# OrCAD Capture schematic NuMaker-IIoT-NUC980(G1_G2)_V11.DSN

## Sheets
1 Block Diagram: size A; title: NK-980IOT; rev: 1.0; company: nuvoTon Technology Corp.; note: Block Diagram
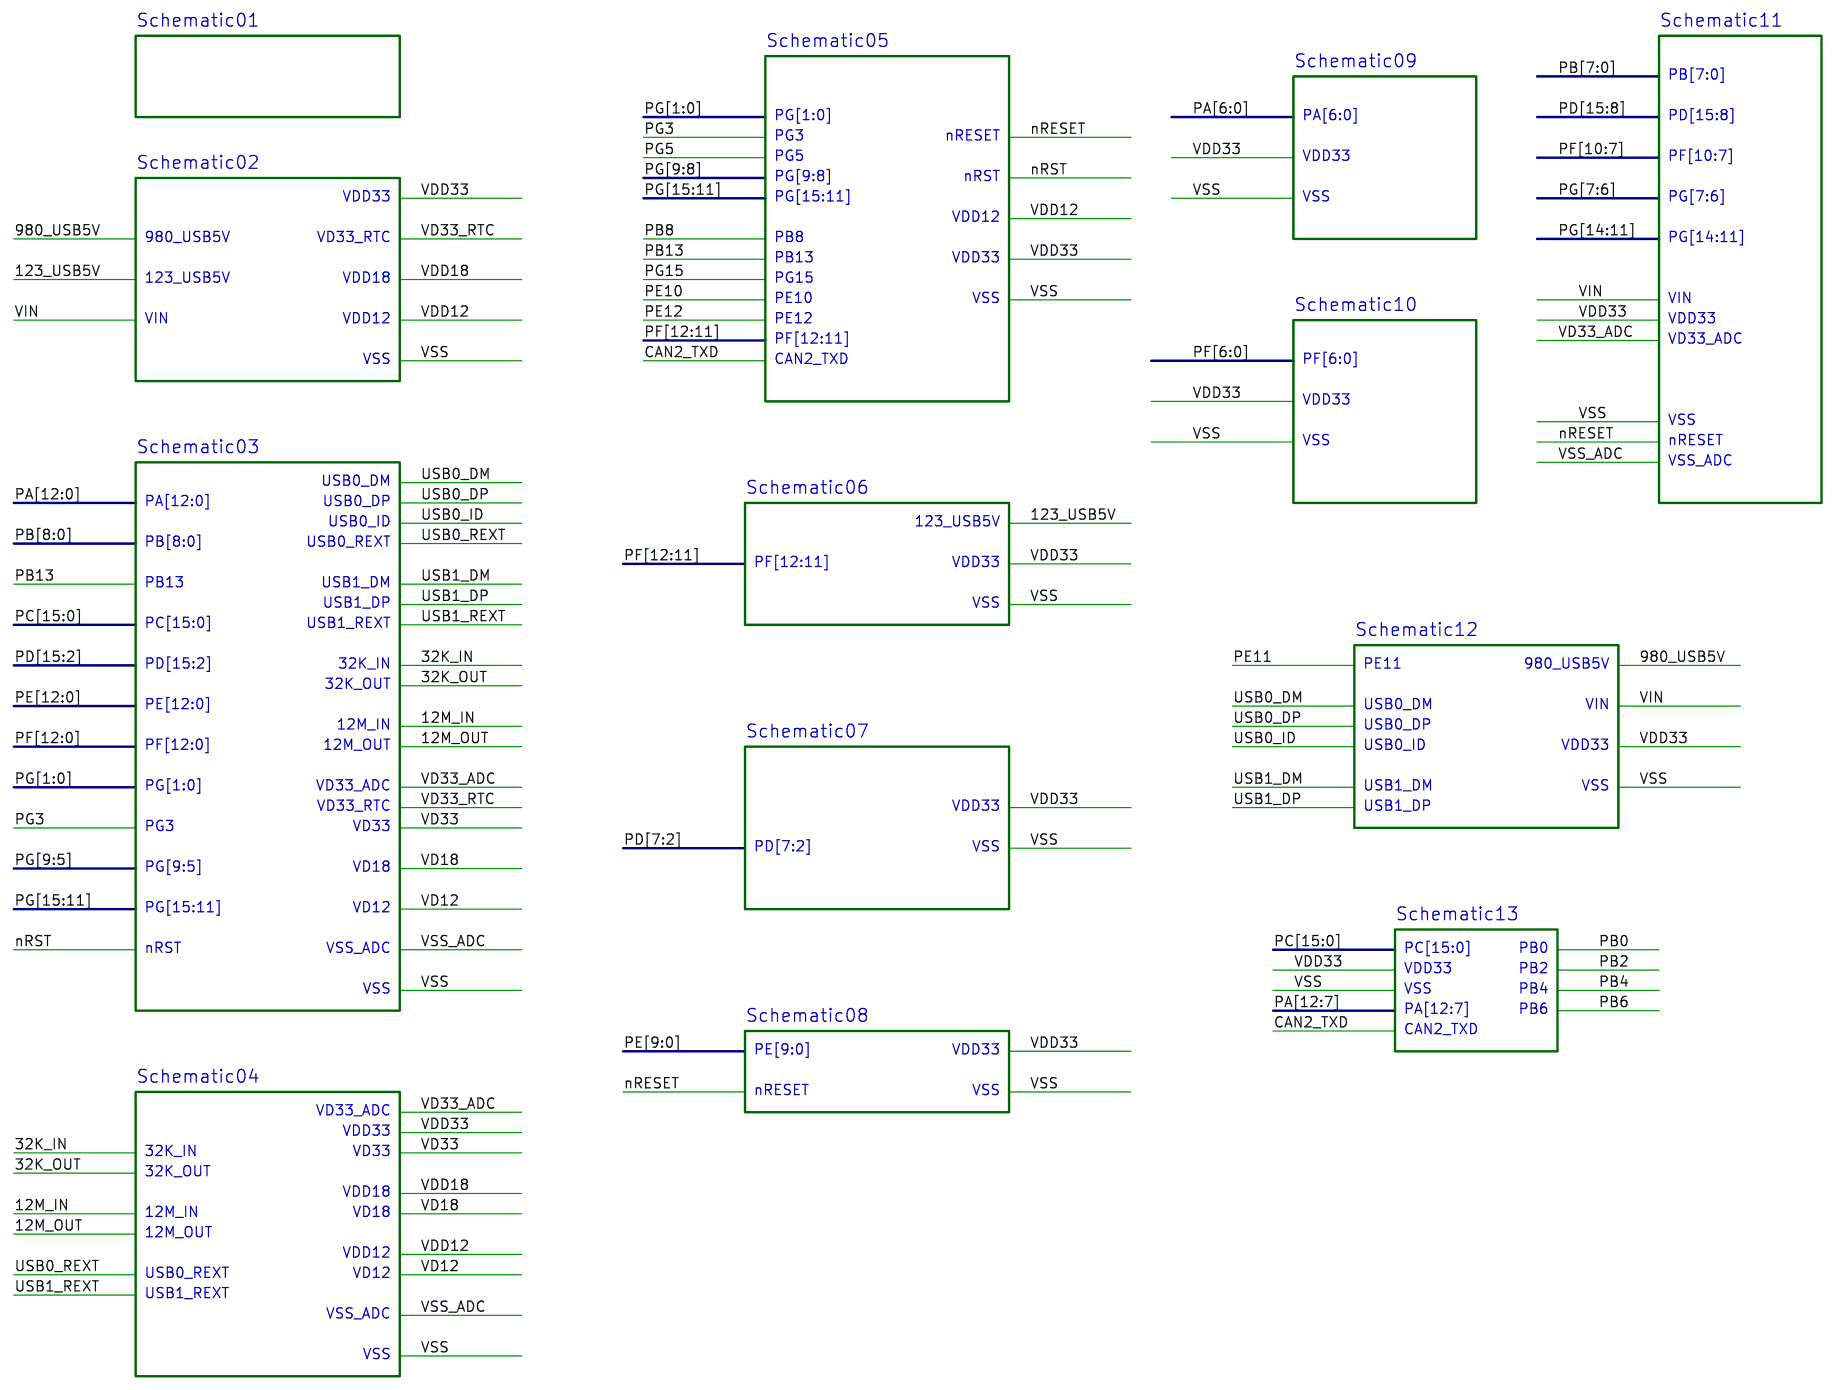
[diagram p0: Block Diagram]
2 Arduino Uno: size A; note: Arduino Uno; block Schematic11
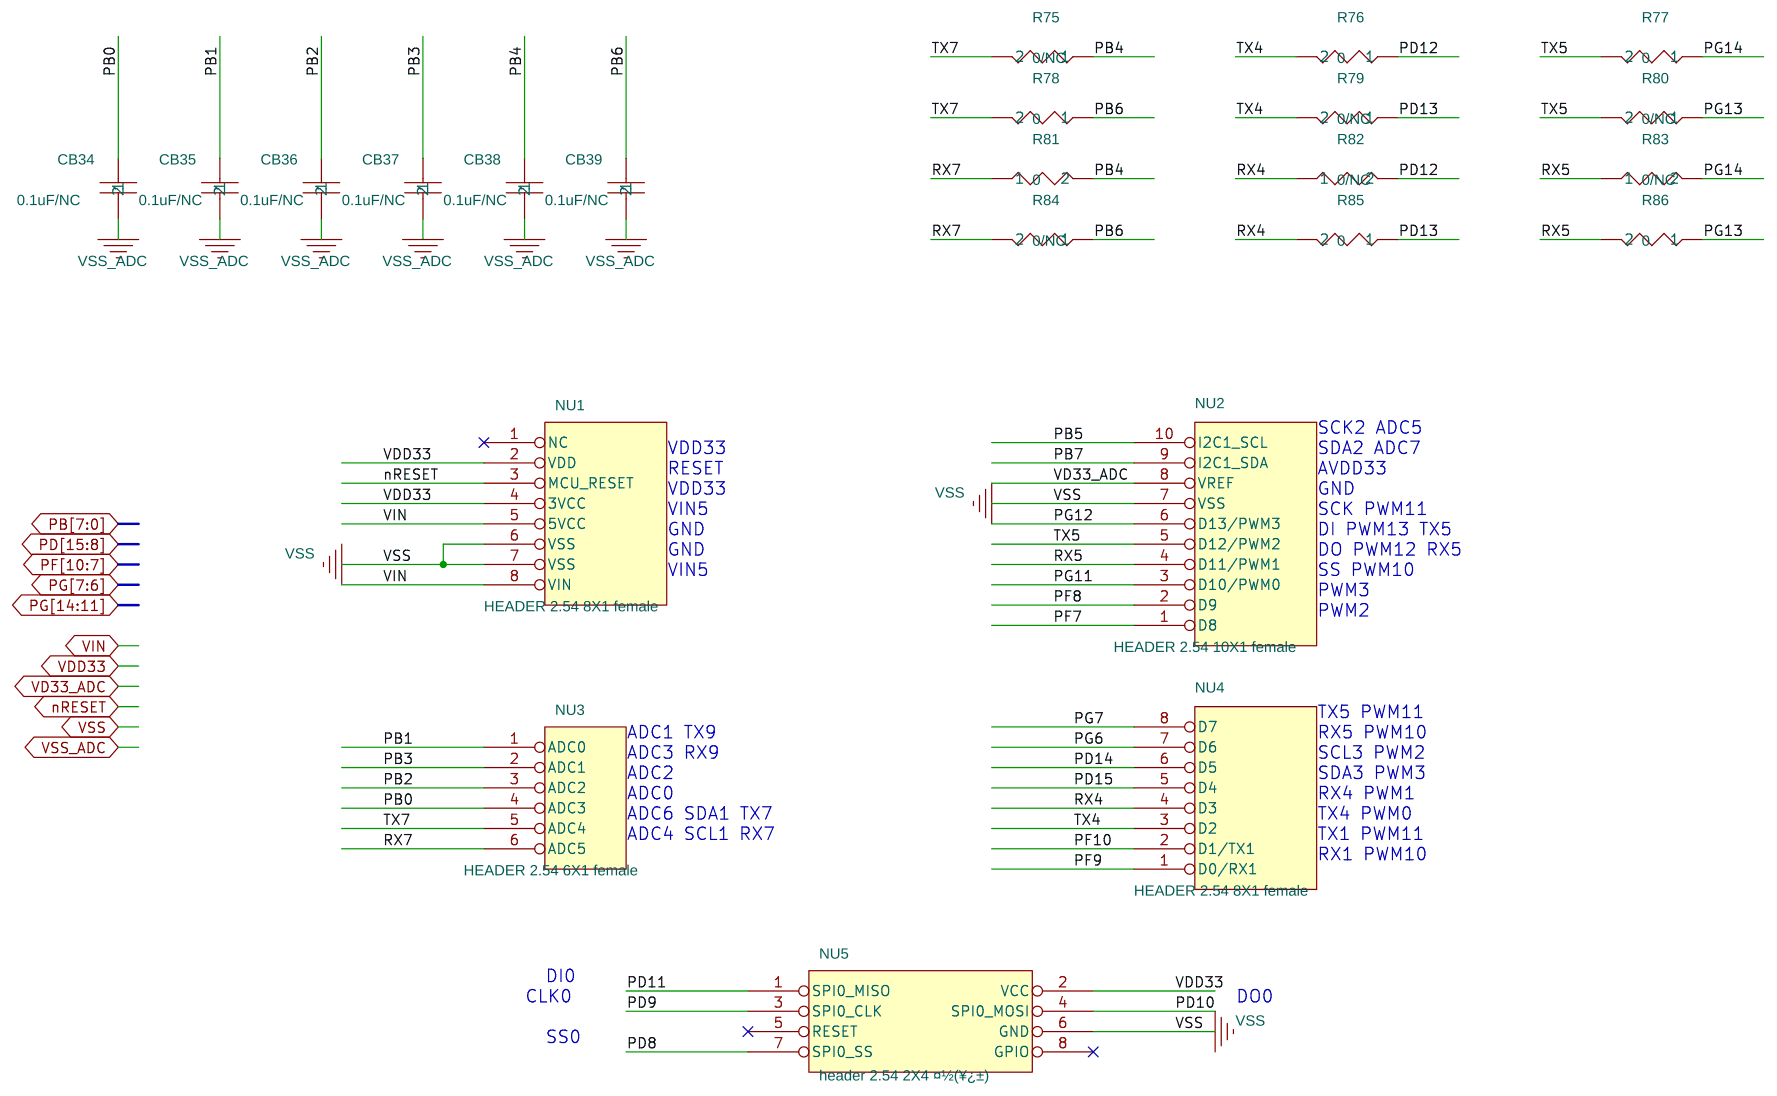
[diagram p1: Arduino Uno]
3 SD_Card: size A; note: SD_Card; block Schematic10
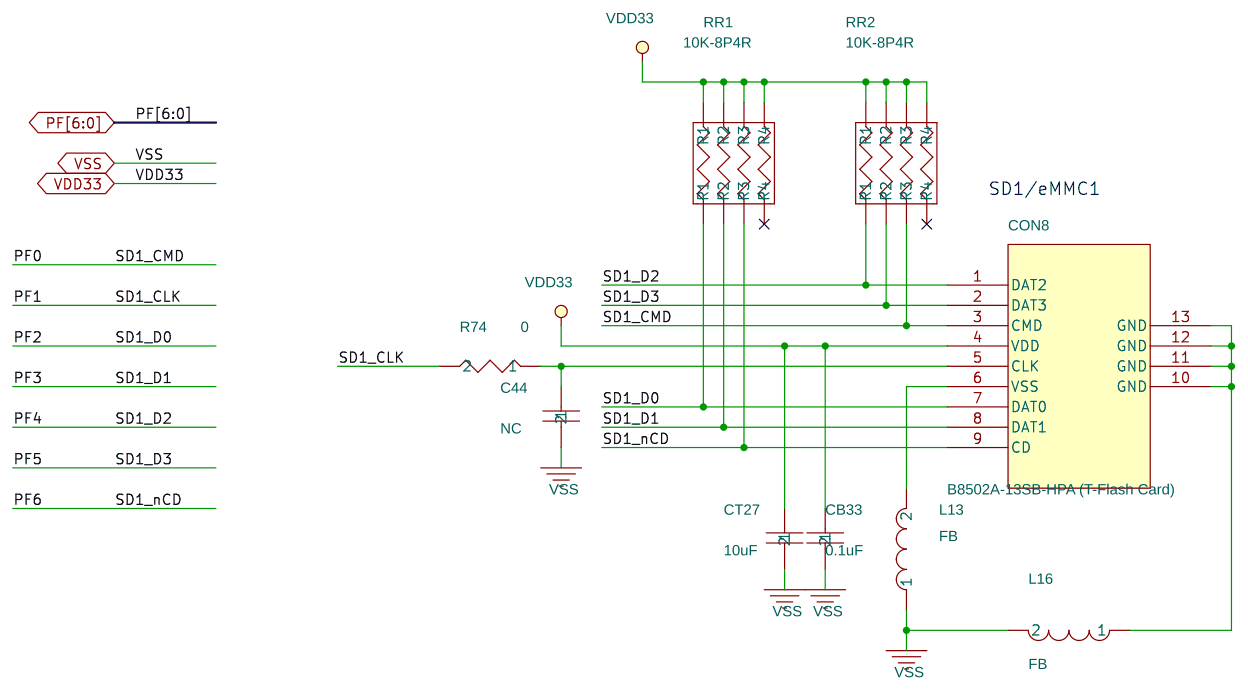
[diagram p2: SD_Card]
4 RMII_PE: size A; note: RMII_PE; block Schematic08
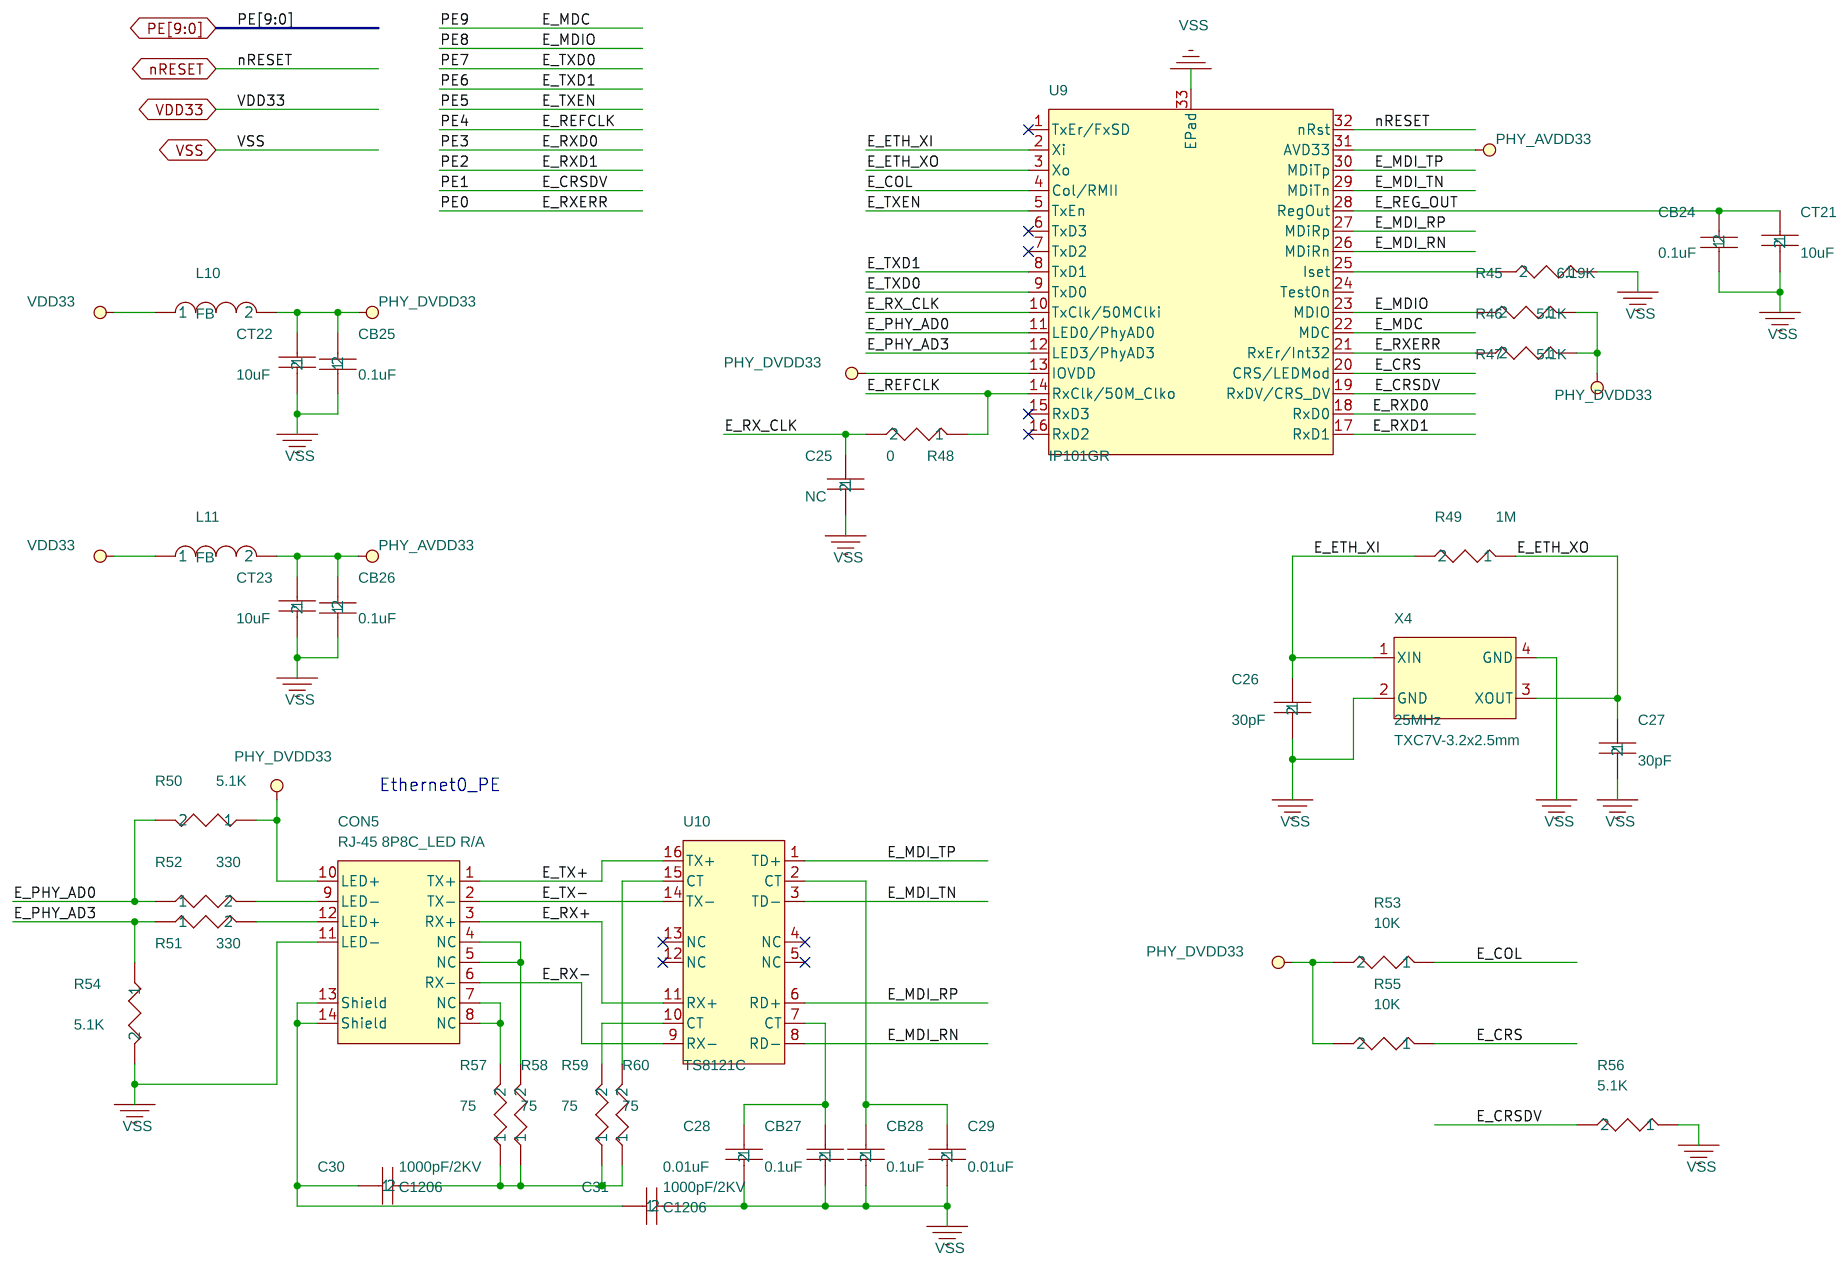
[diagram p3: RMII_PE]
5 Power Filter: size A; note: Power Filter; block Schematic04
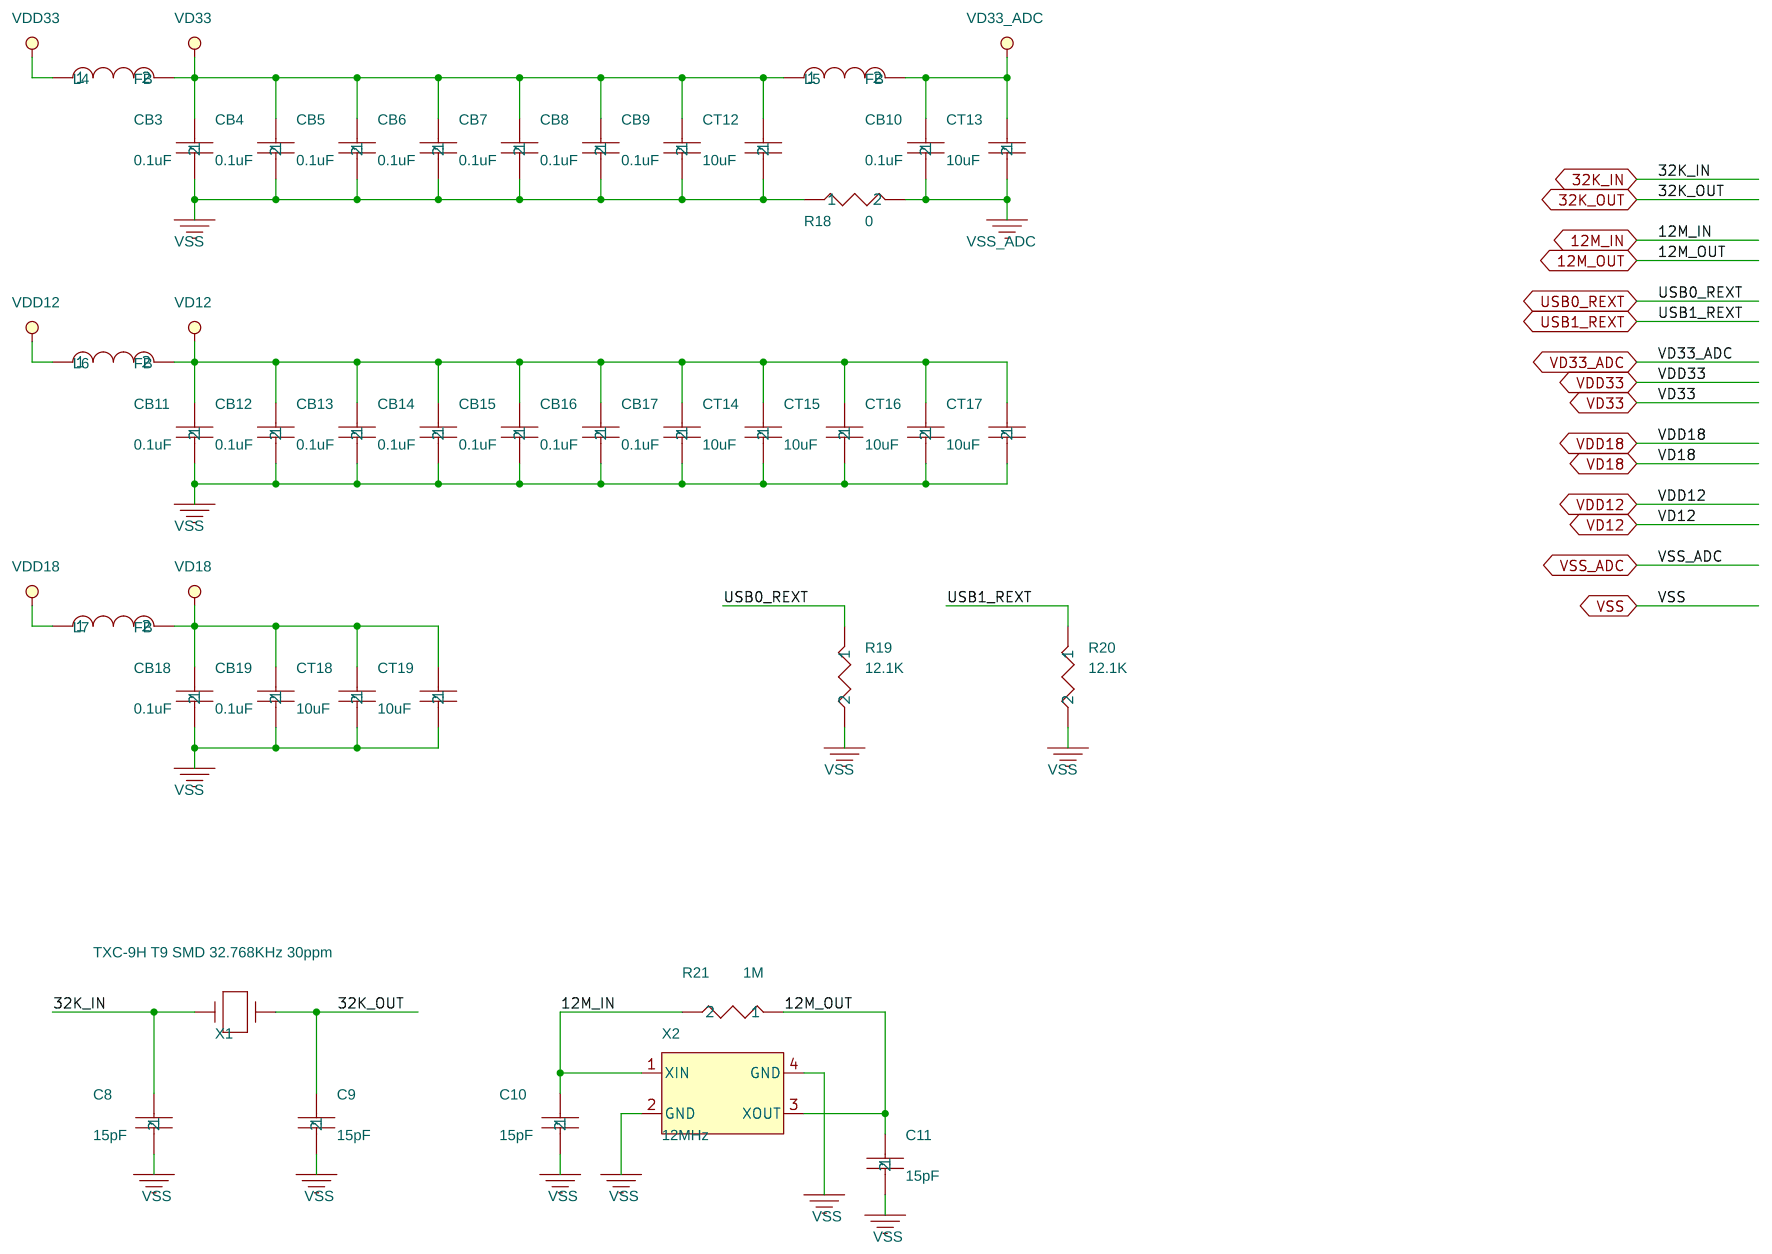
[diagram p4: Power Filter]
6 I2S, I2C_0: size B; note: I2S, I2C_0; block Schematic09
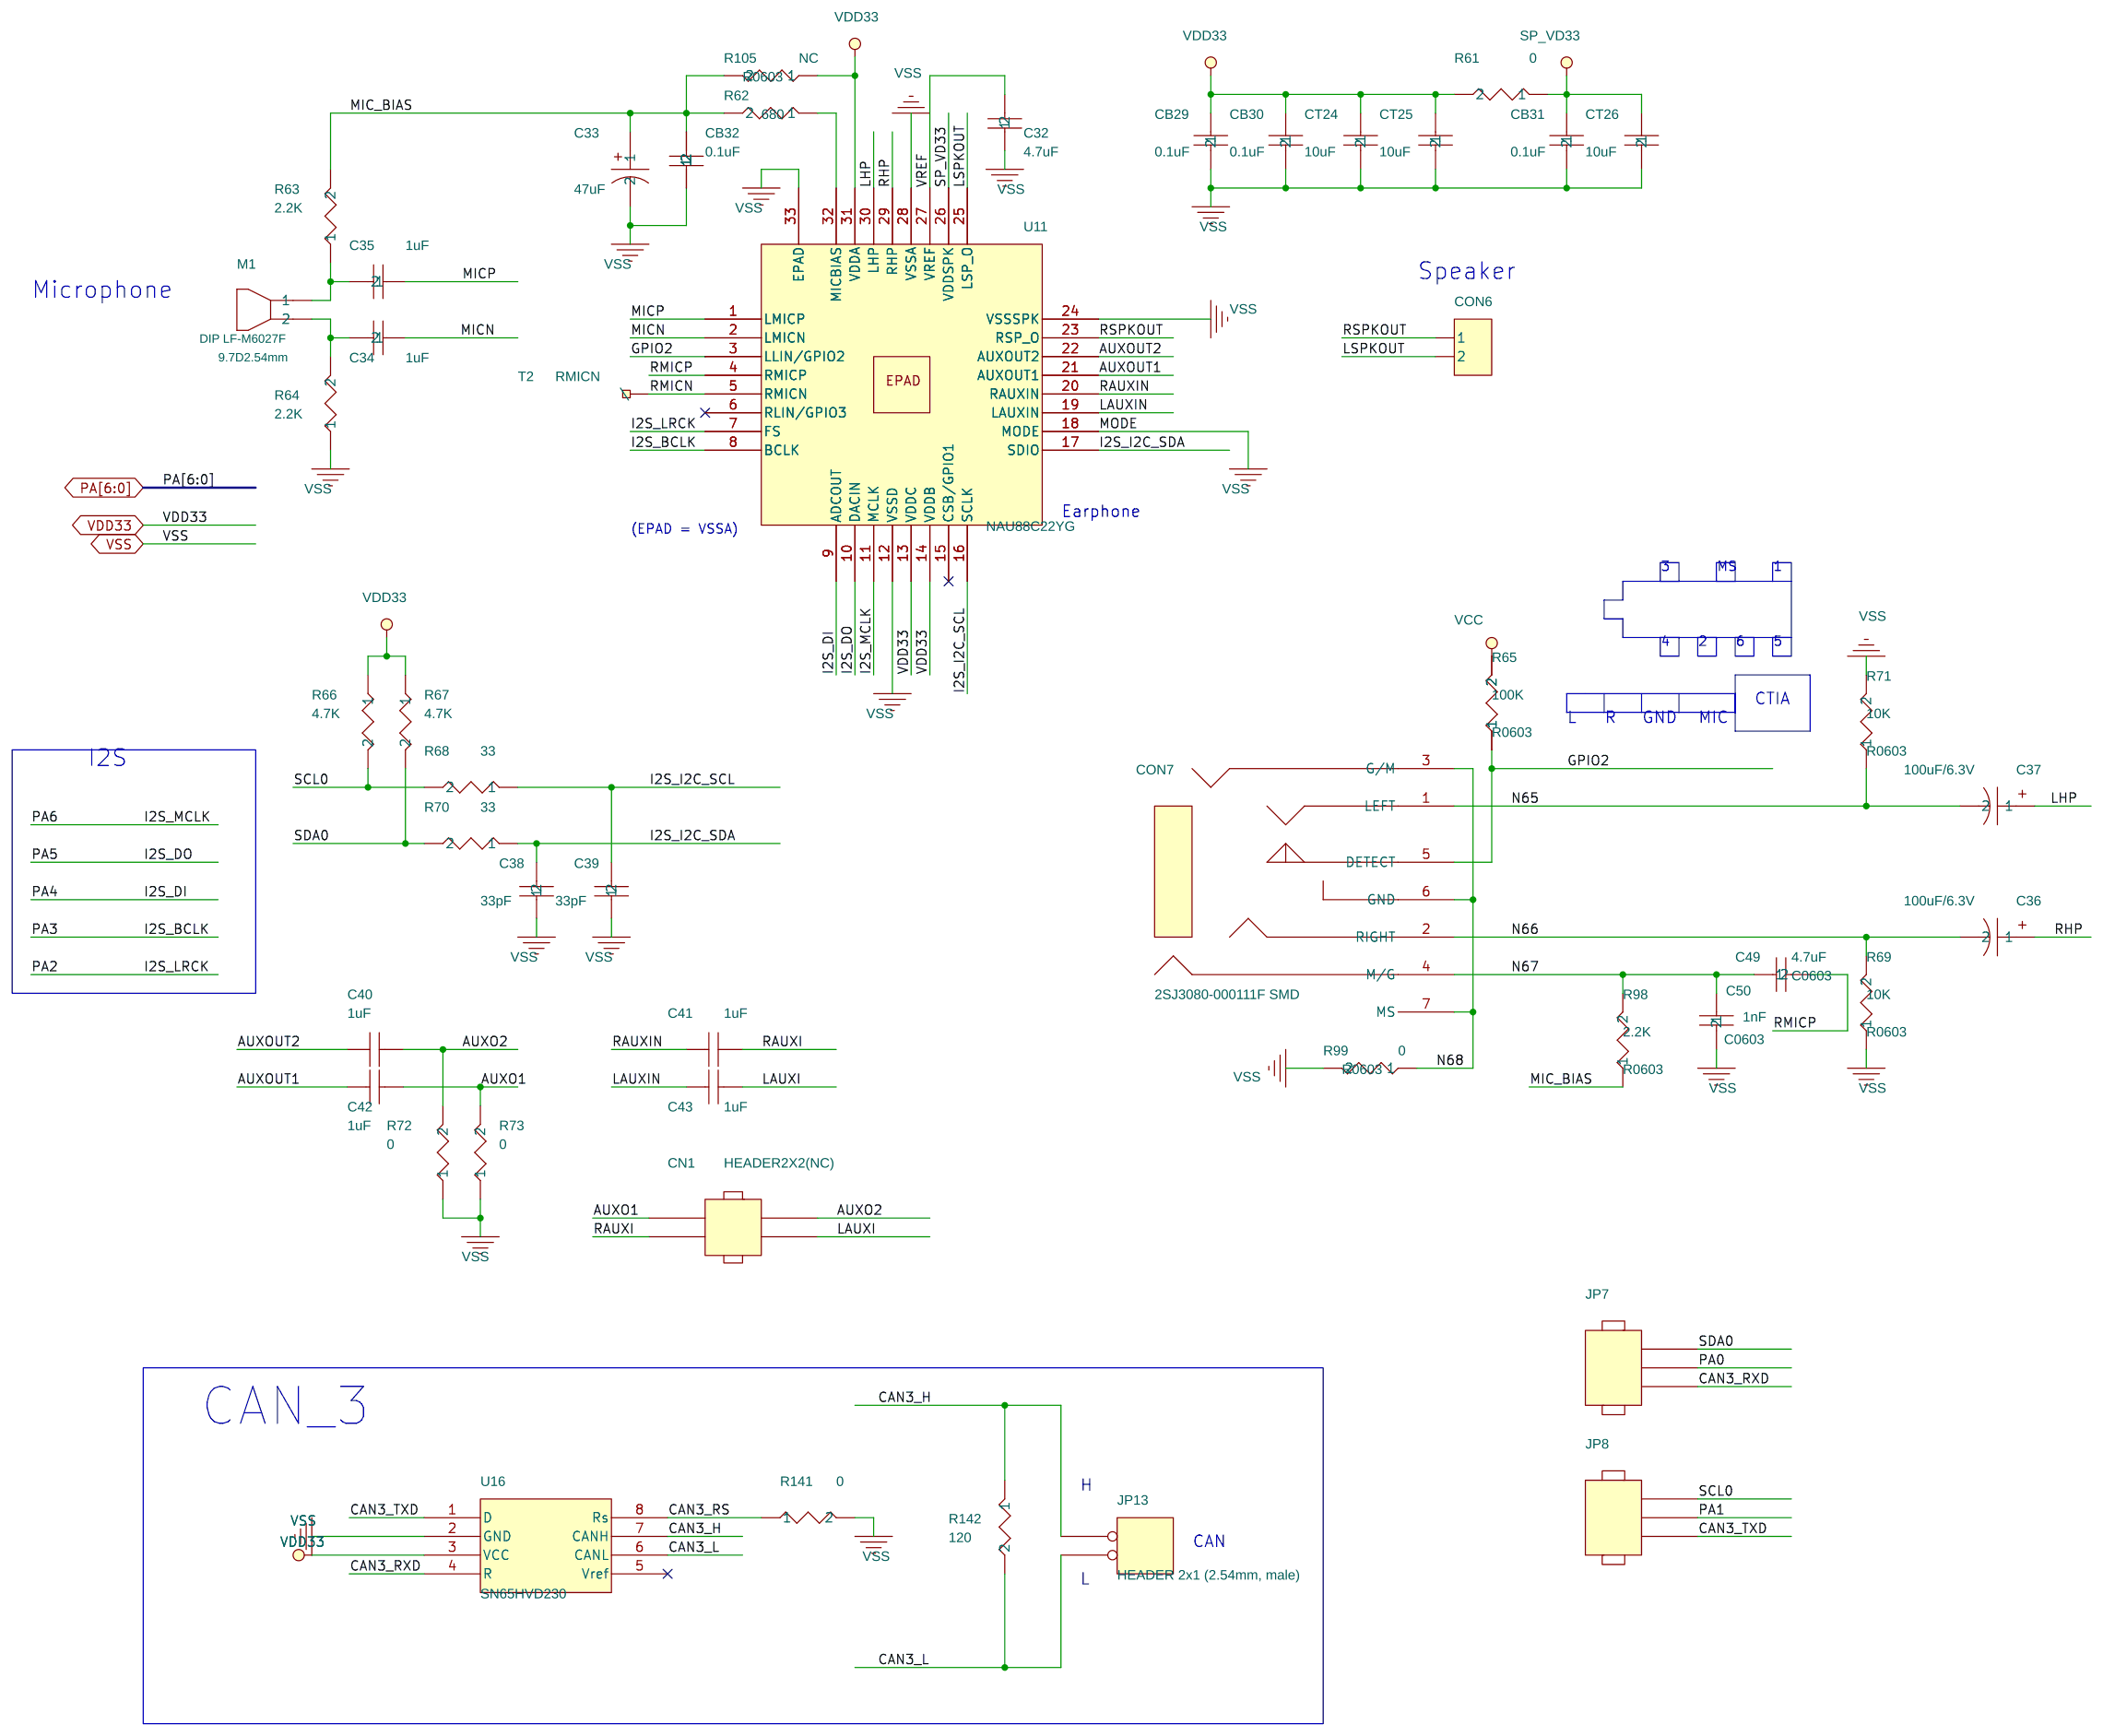
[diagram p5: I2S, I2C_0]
7 SPI Nand Flash: size A; note: SPI Nand Flash; block Schematic07
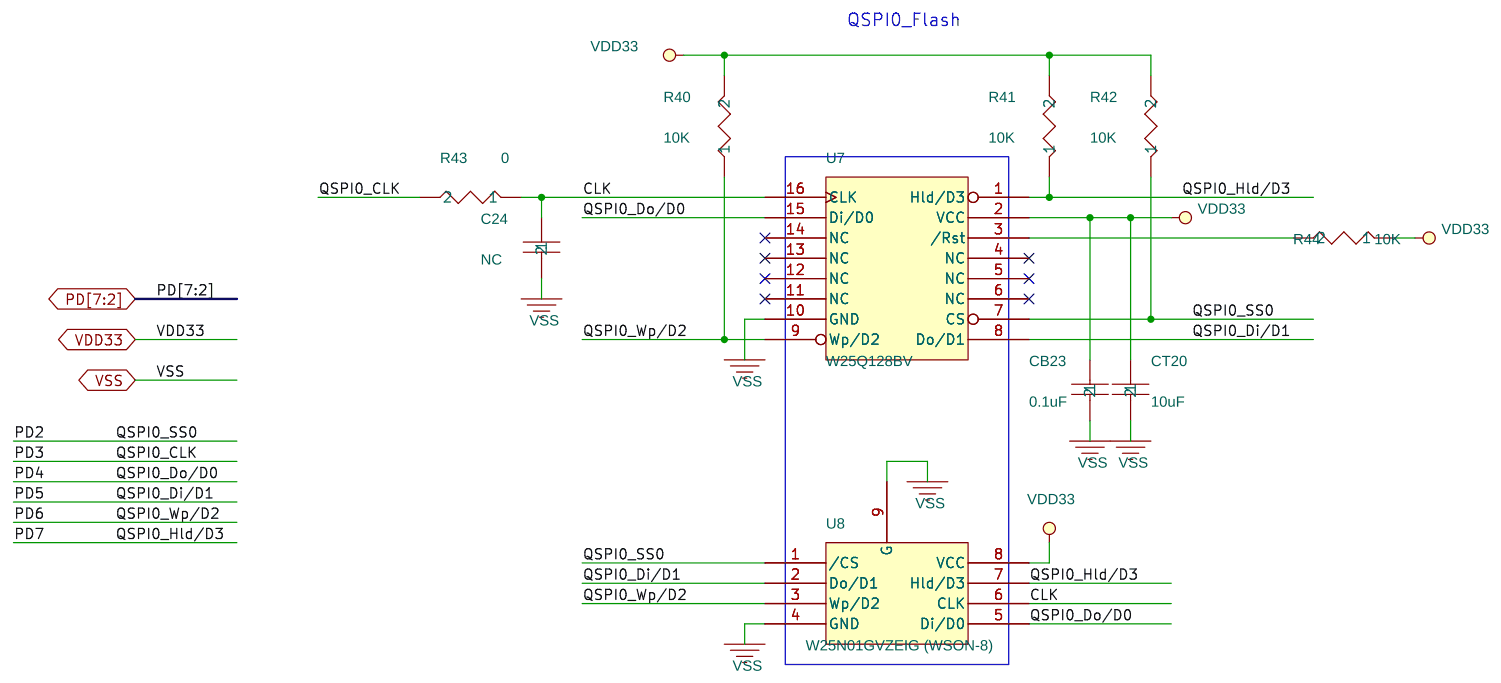
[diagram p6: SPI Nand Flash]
8 EBI_Connect: size A; note: EBI_Connect; block Schematic13
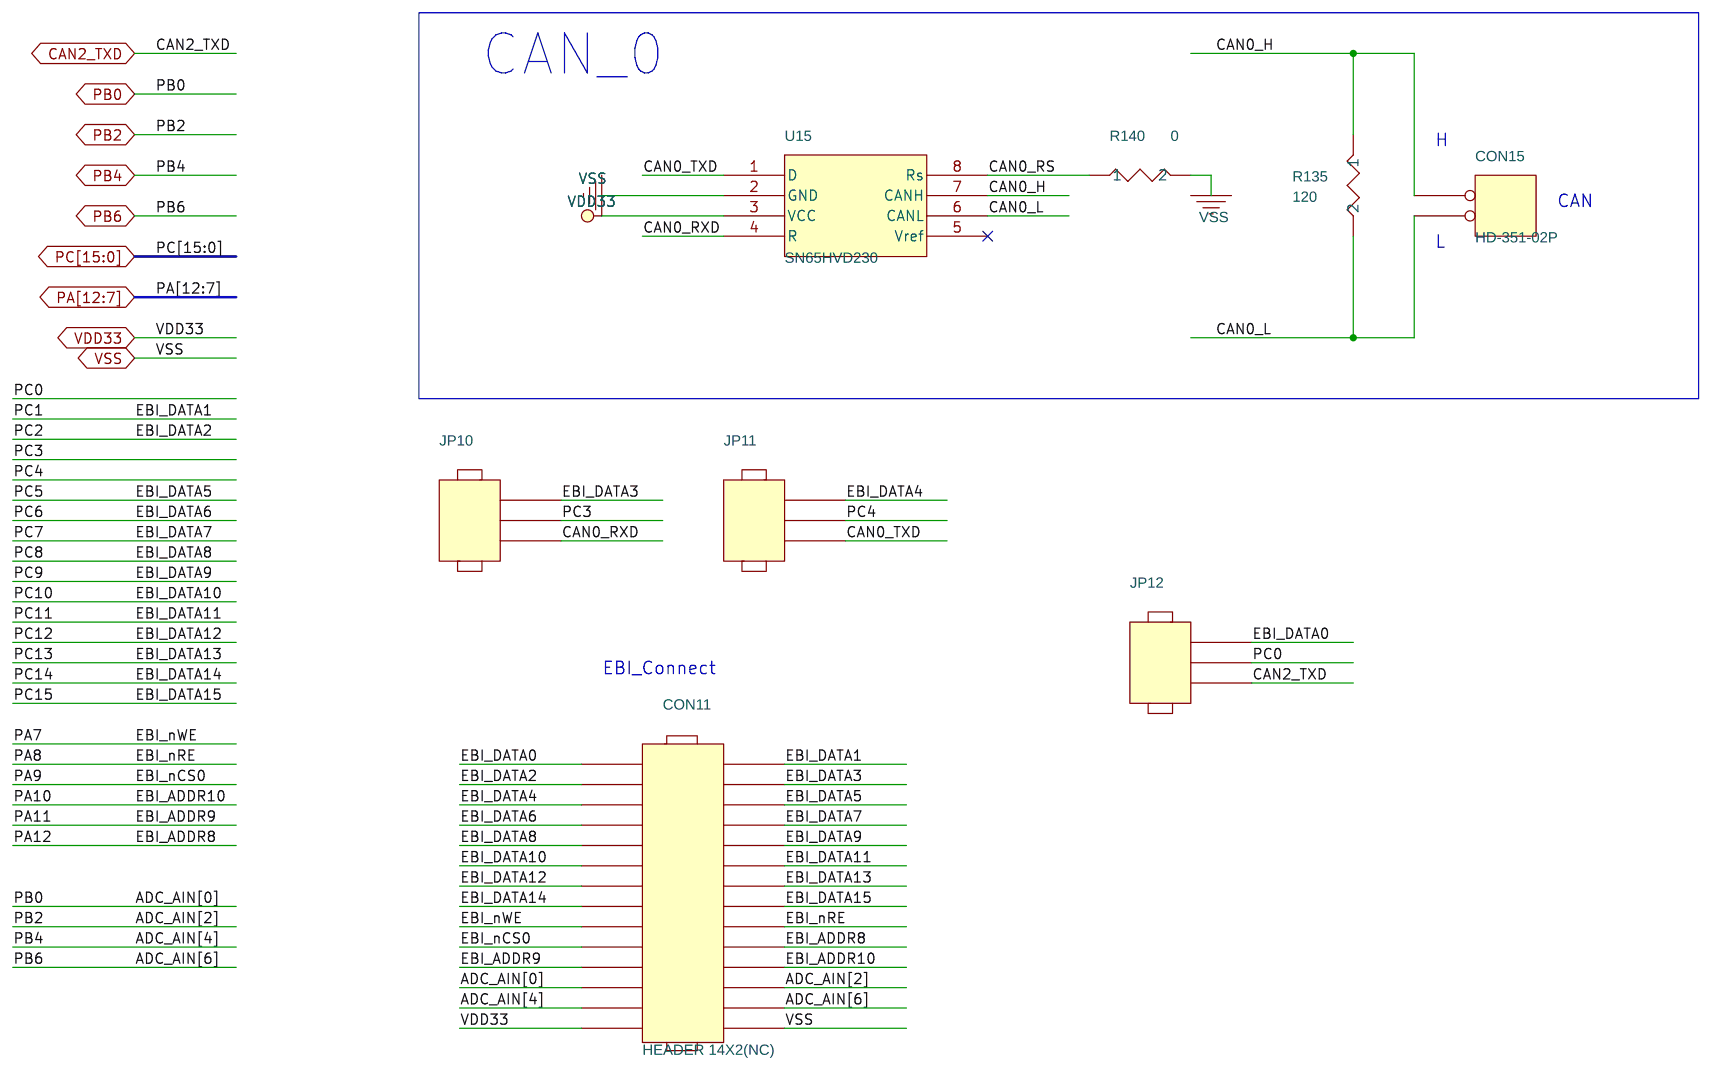
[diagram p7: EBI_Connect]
9 GPIO List: note: GPIO List
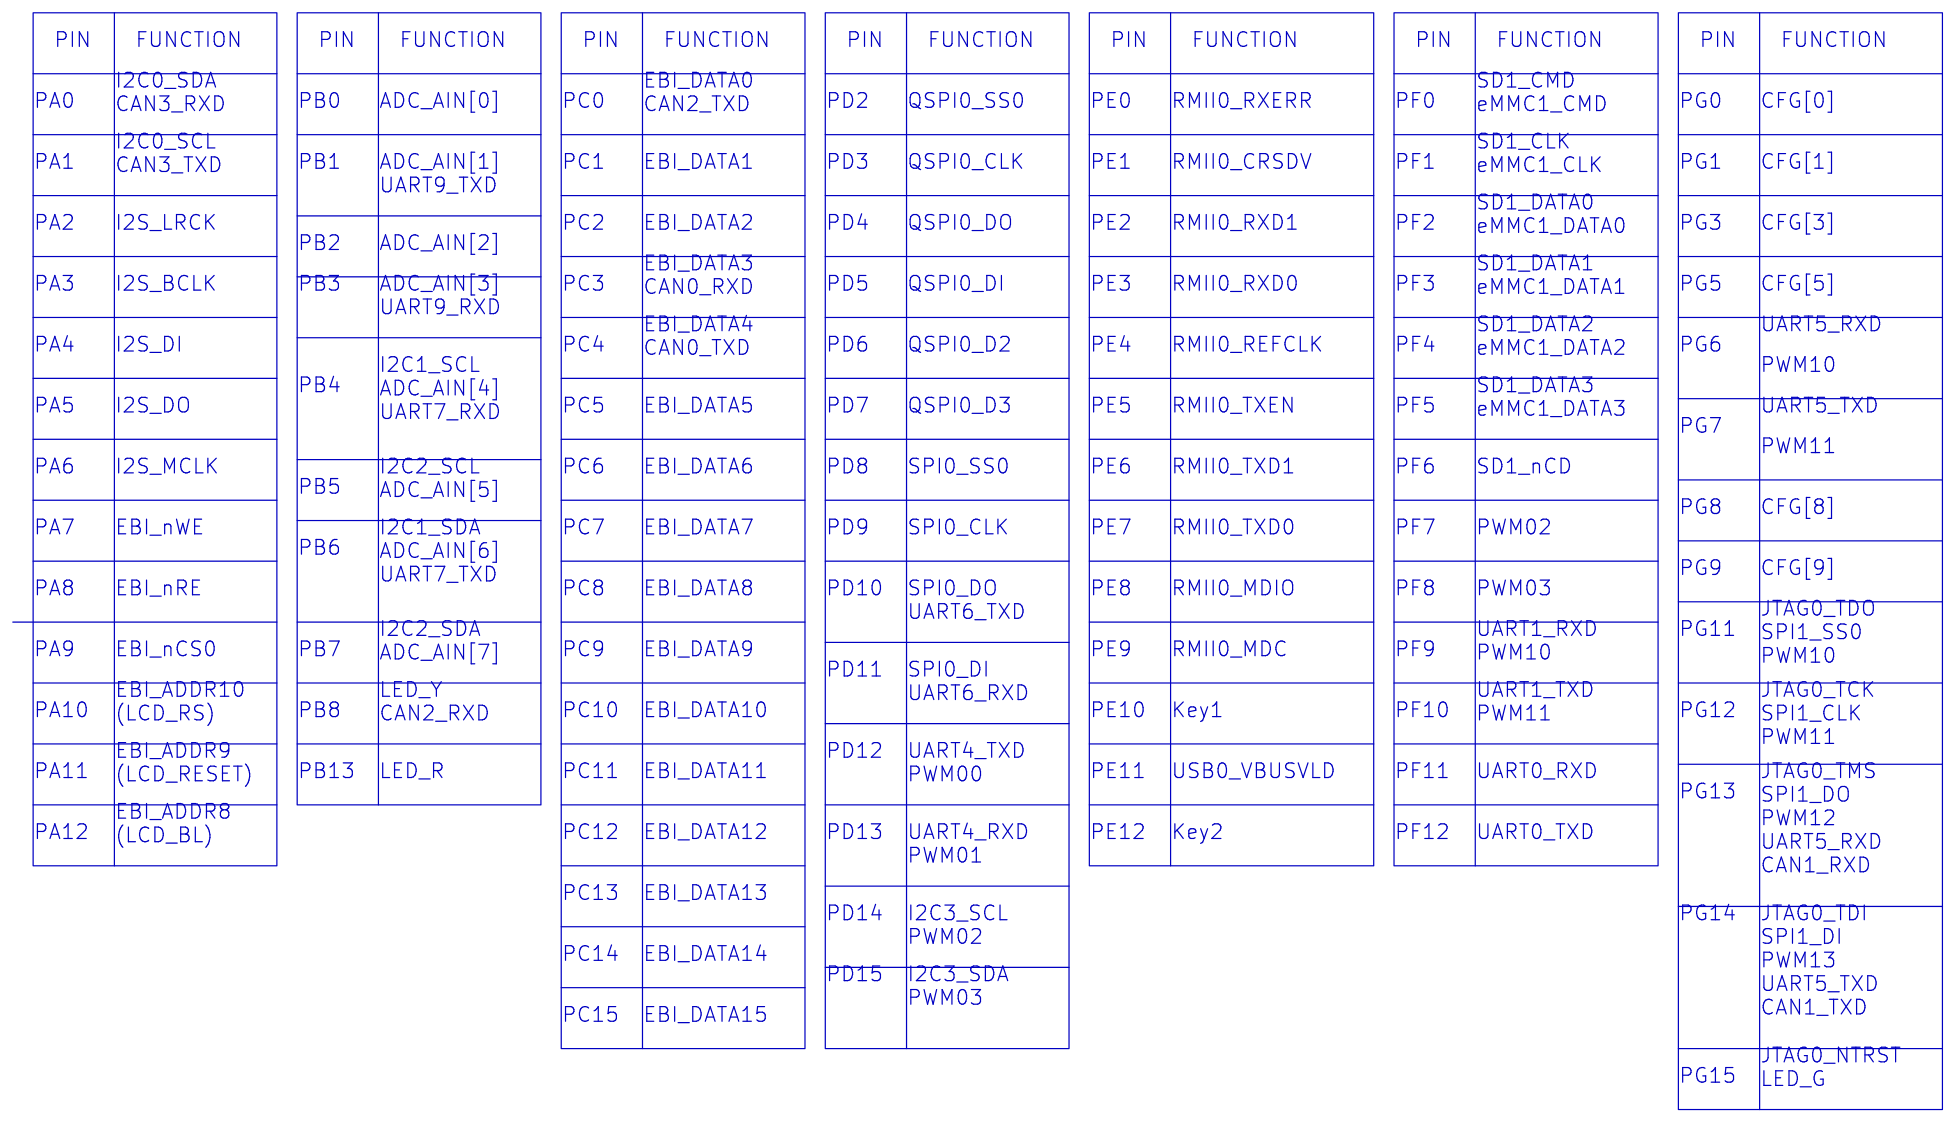
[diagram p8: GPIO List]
10 Power: size A; note: Power; block Schematic02
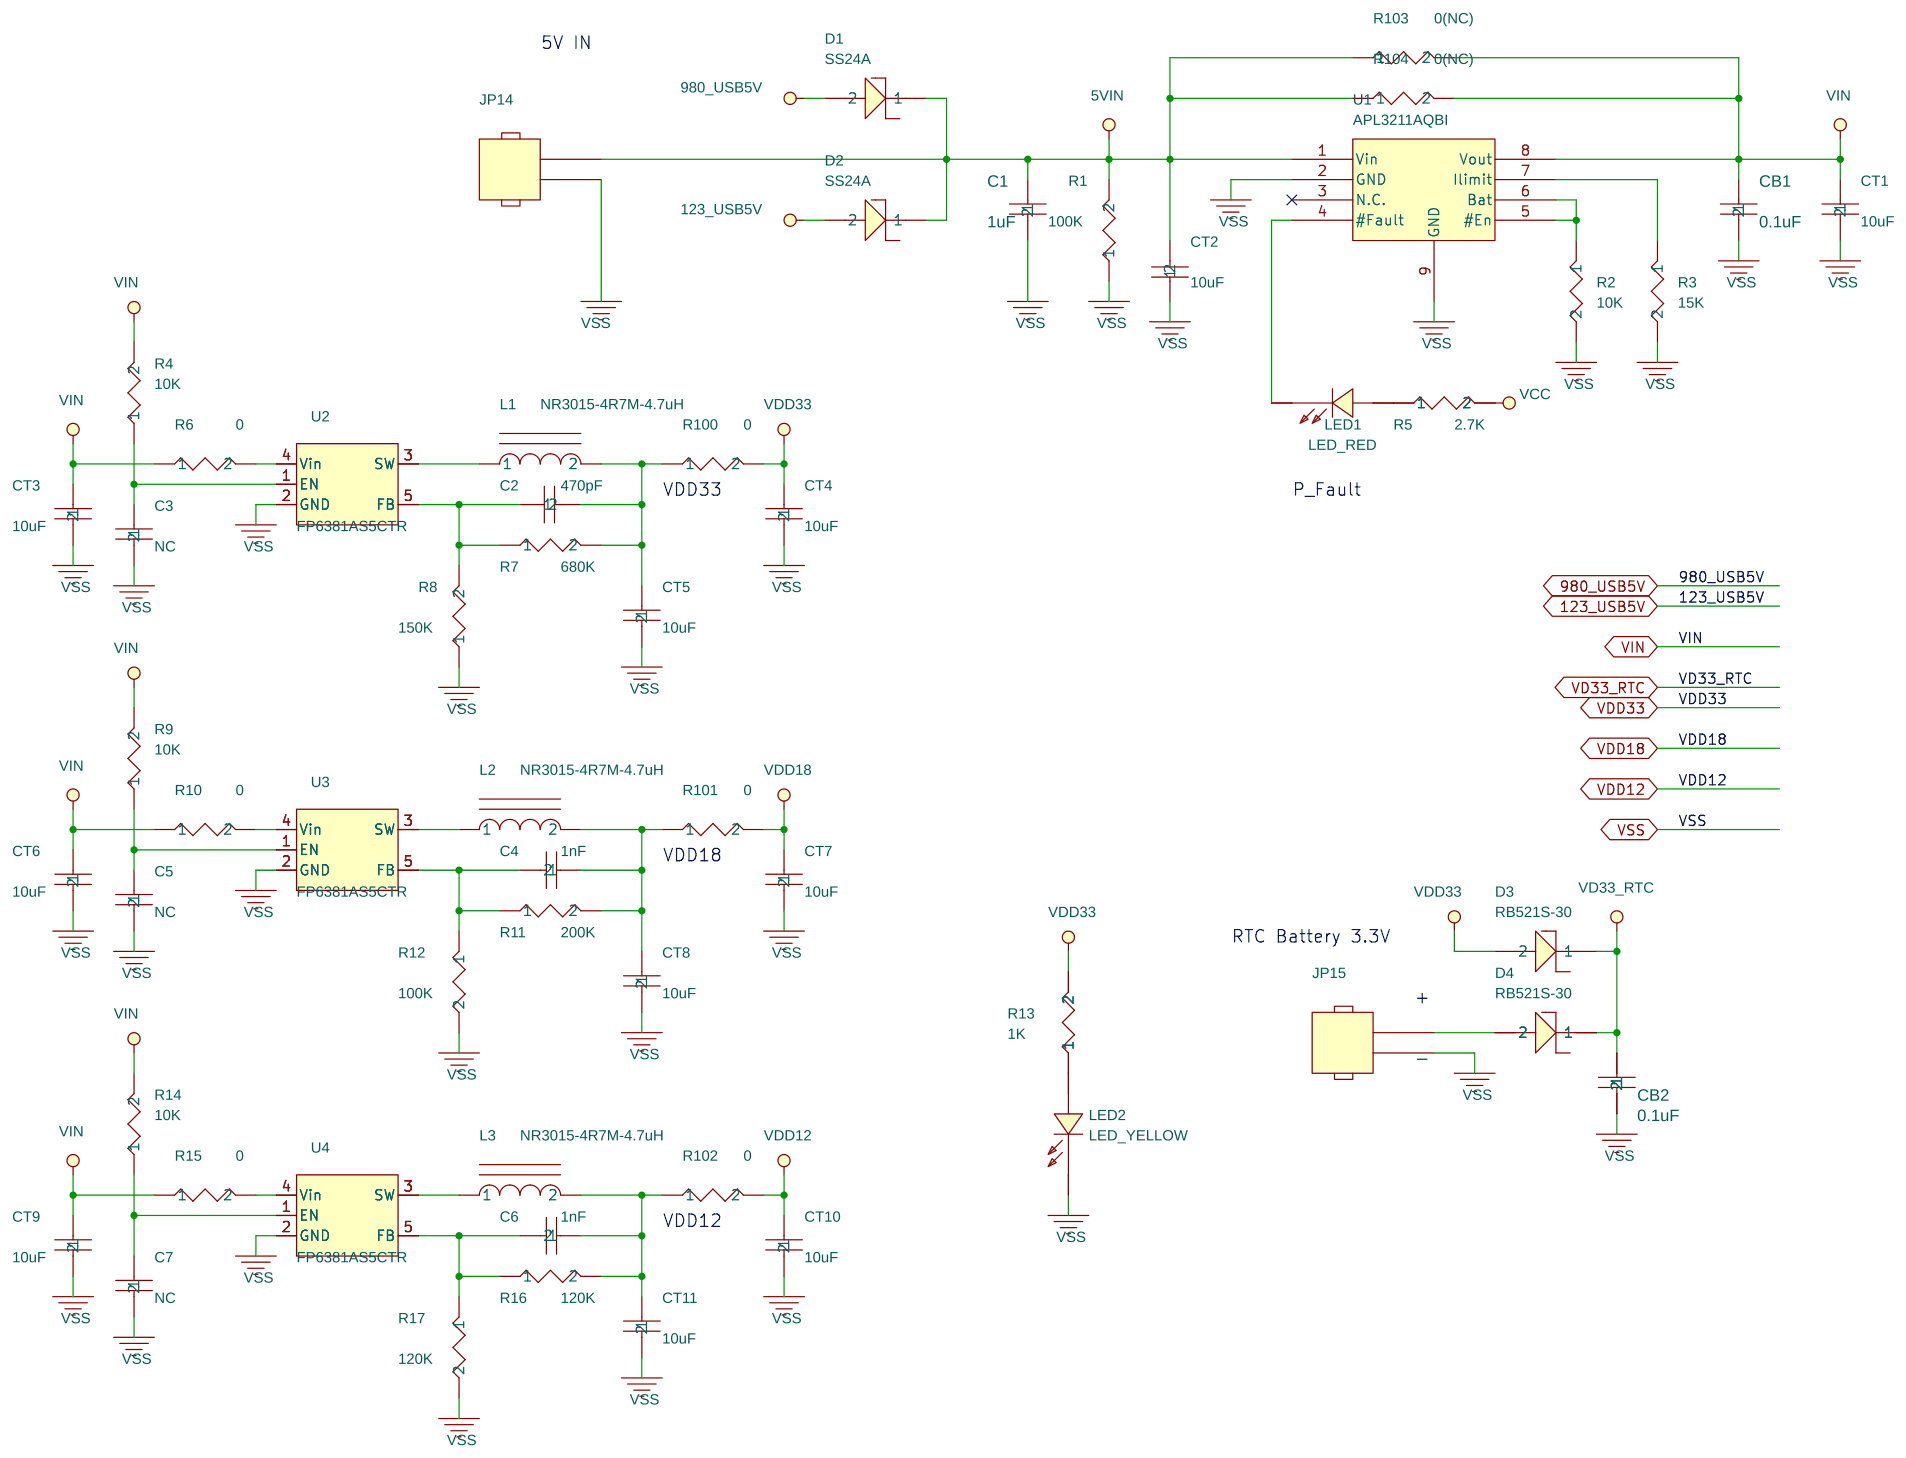
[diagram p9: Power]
11 Configure: size B; note: Configure; block Schematic05
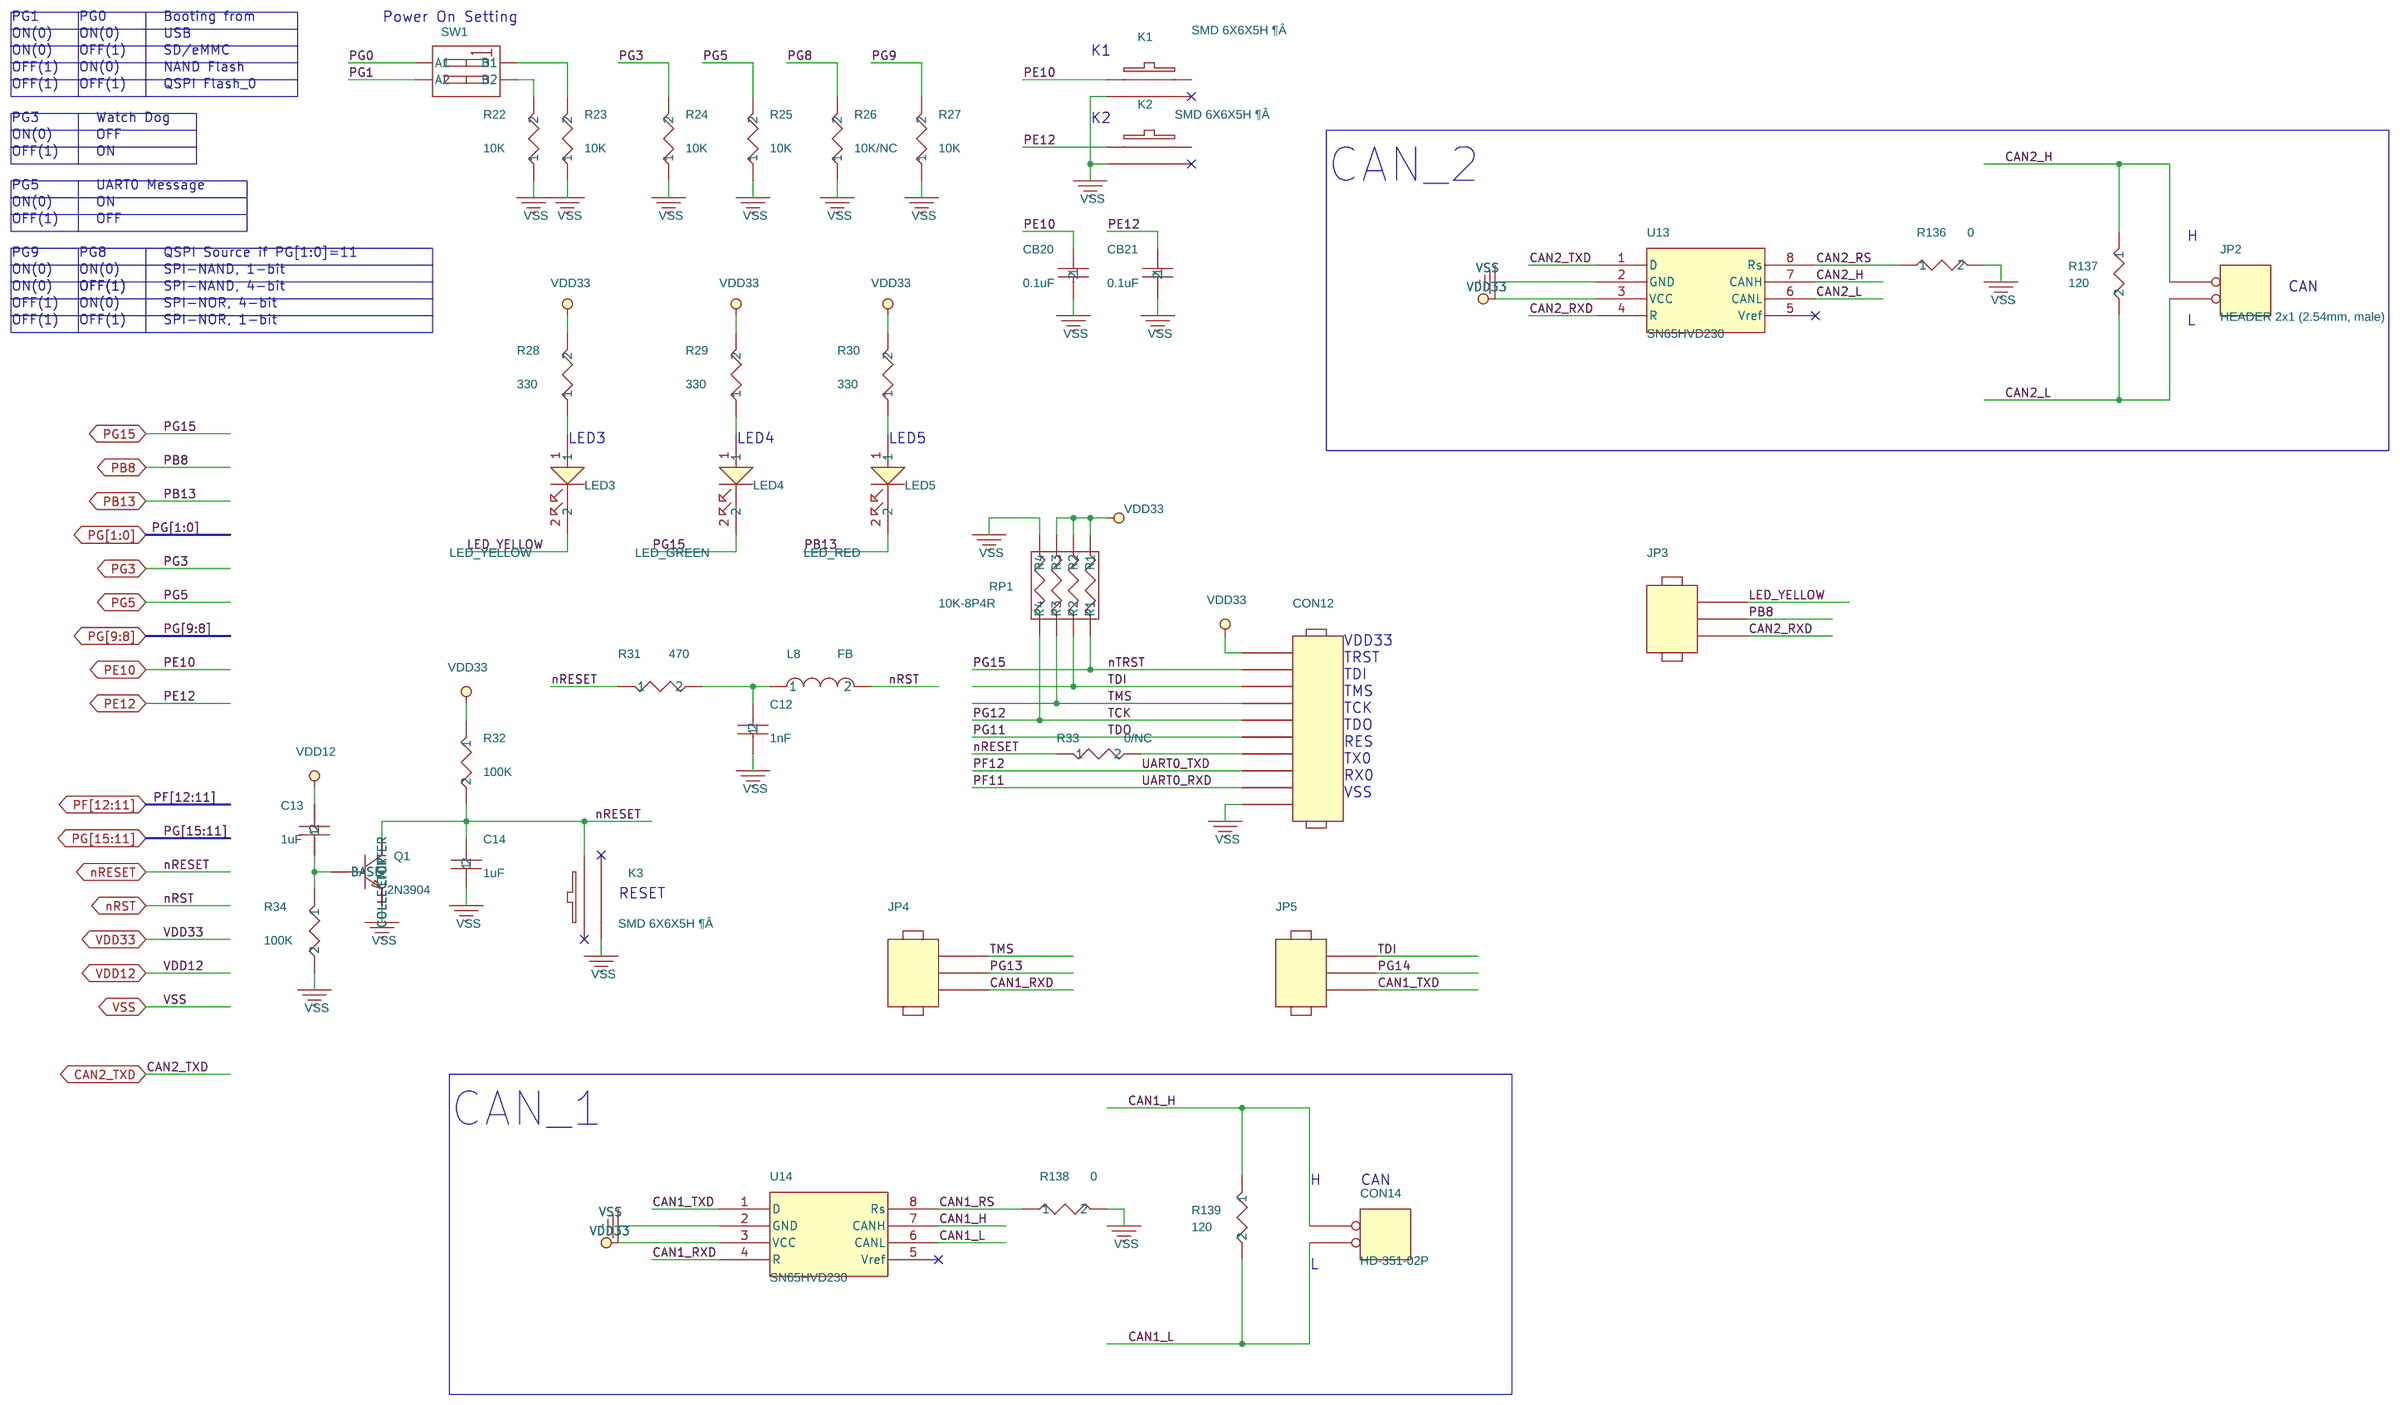
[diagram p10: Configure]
12 USB: size B; note: USB; block Schematic12
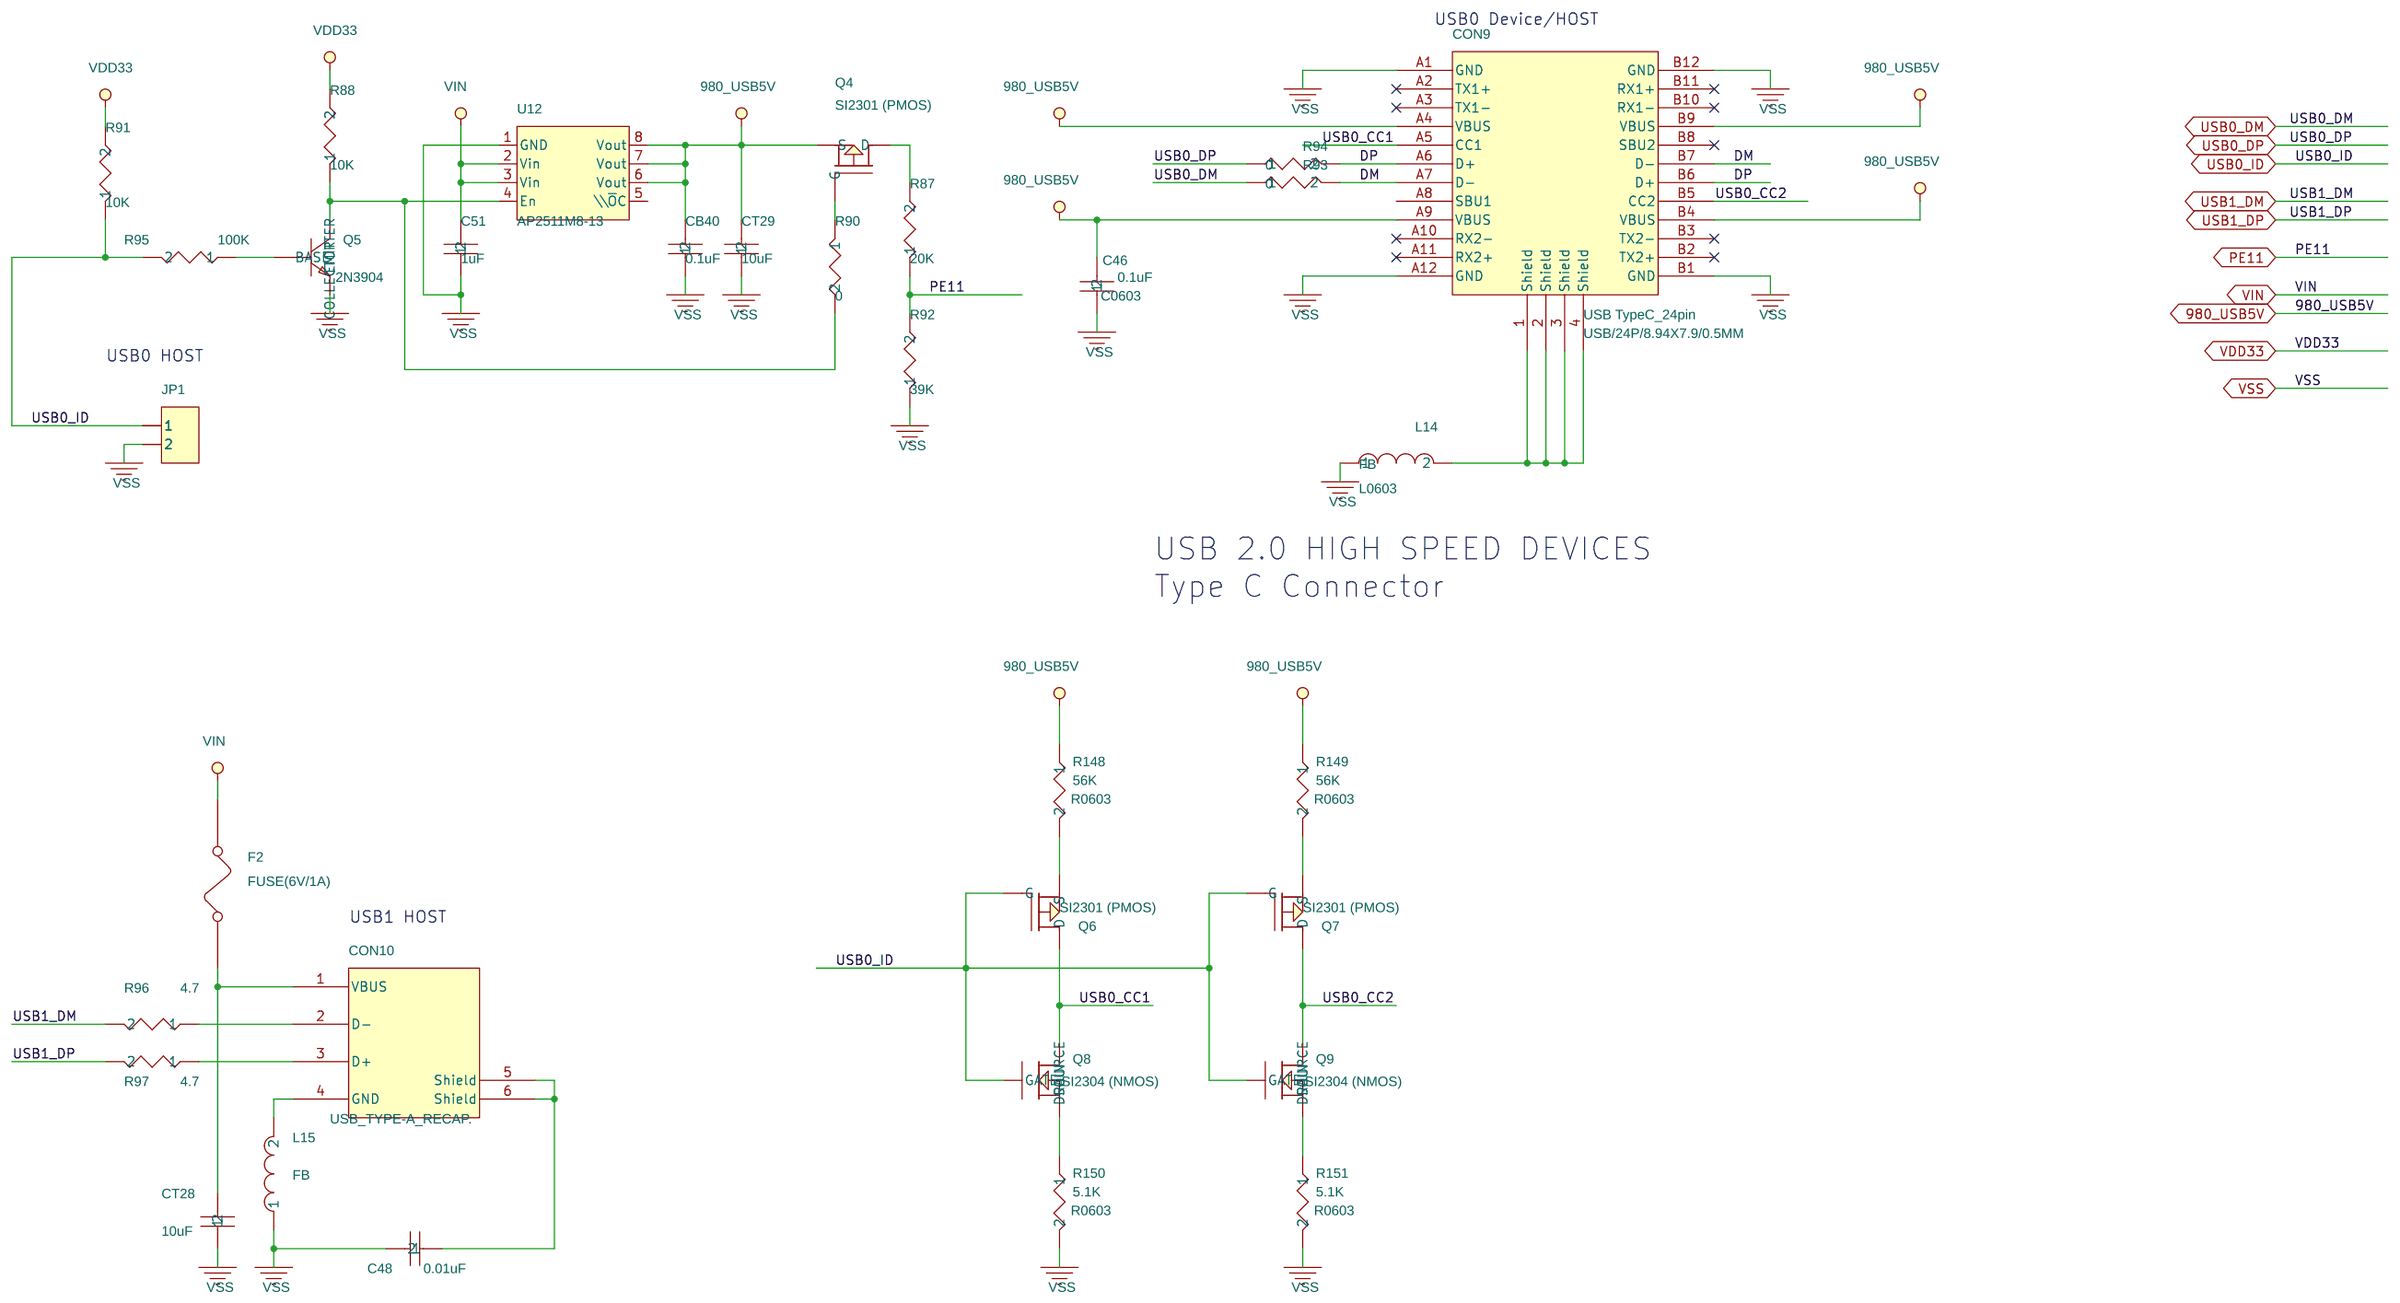
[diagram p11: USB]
13 NUC980DK: size Custom; note: NUC980DK; block Schematic03
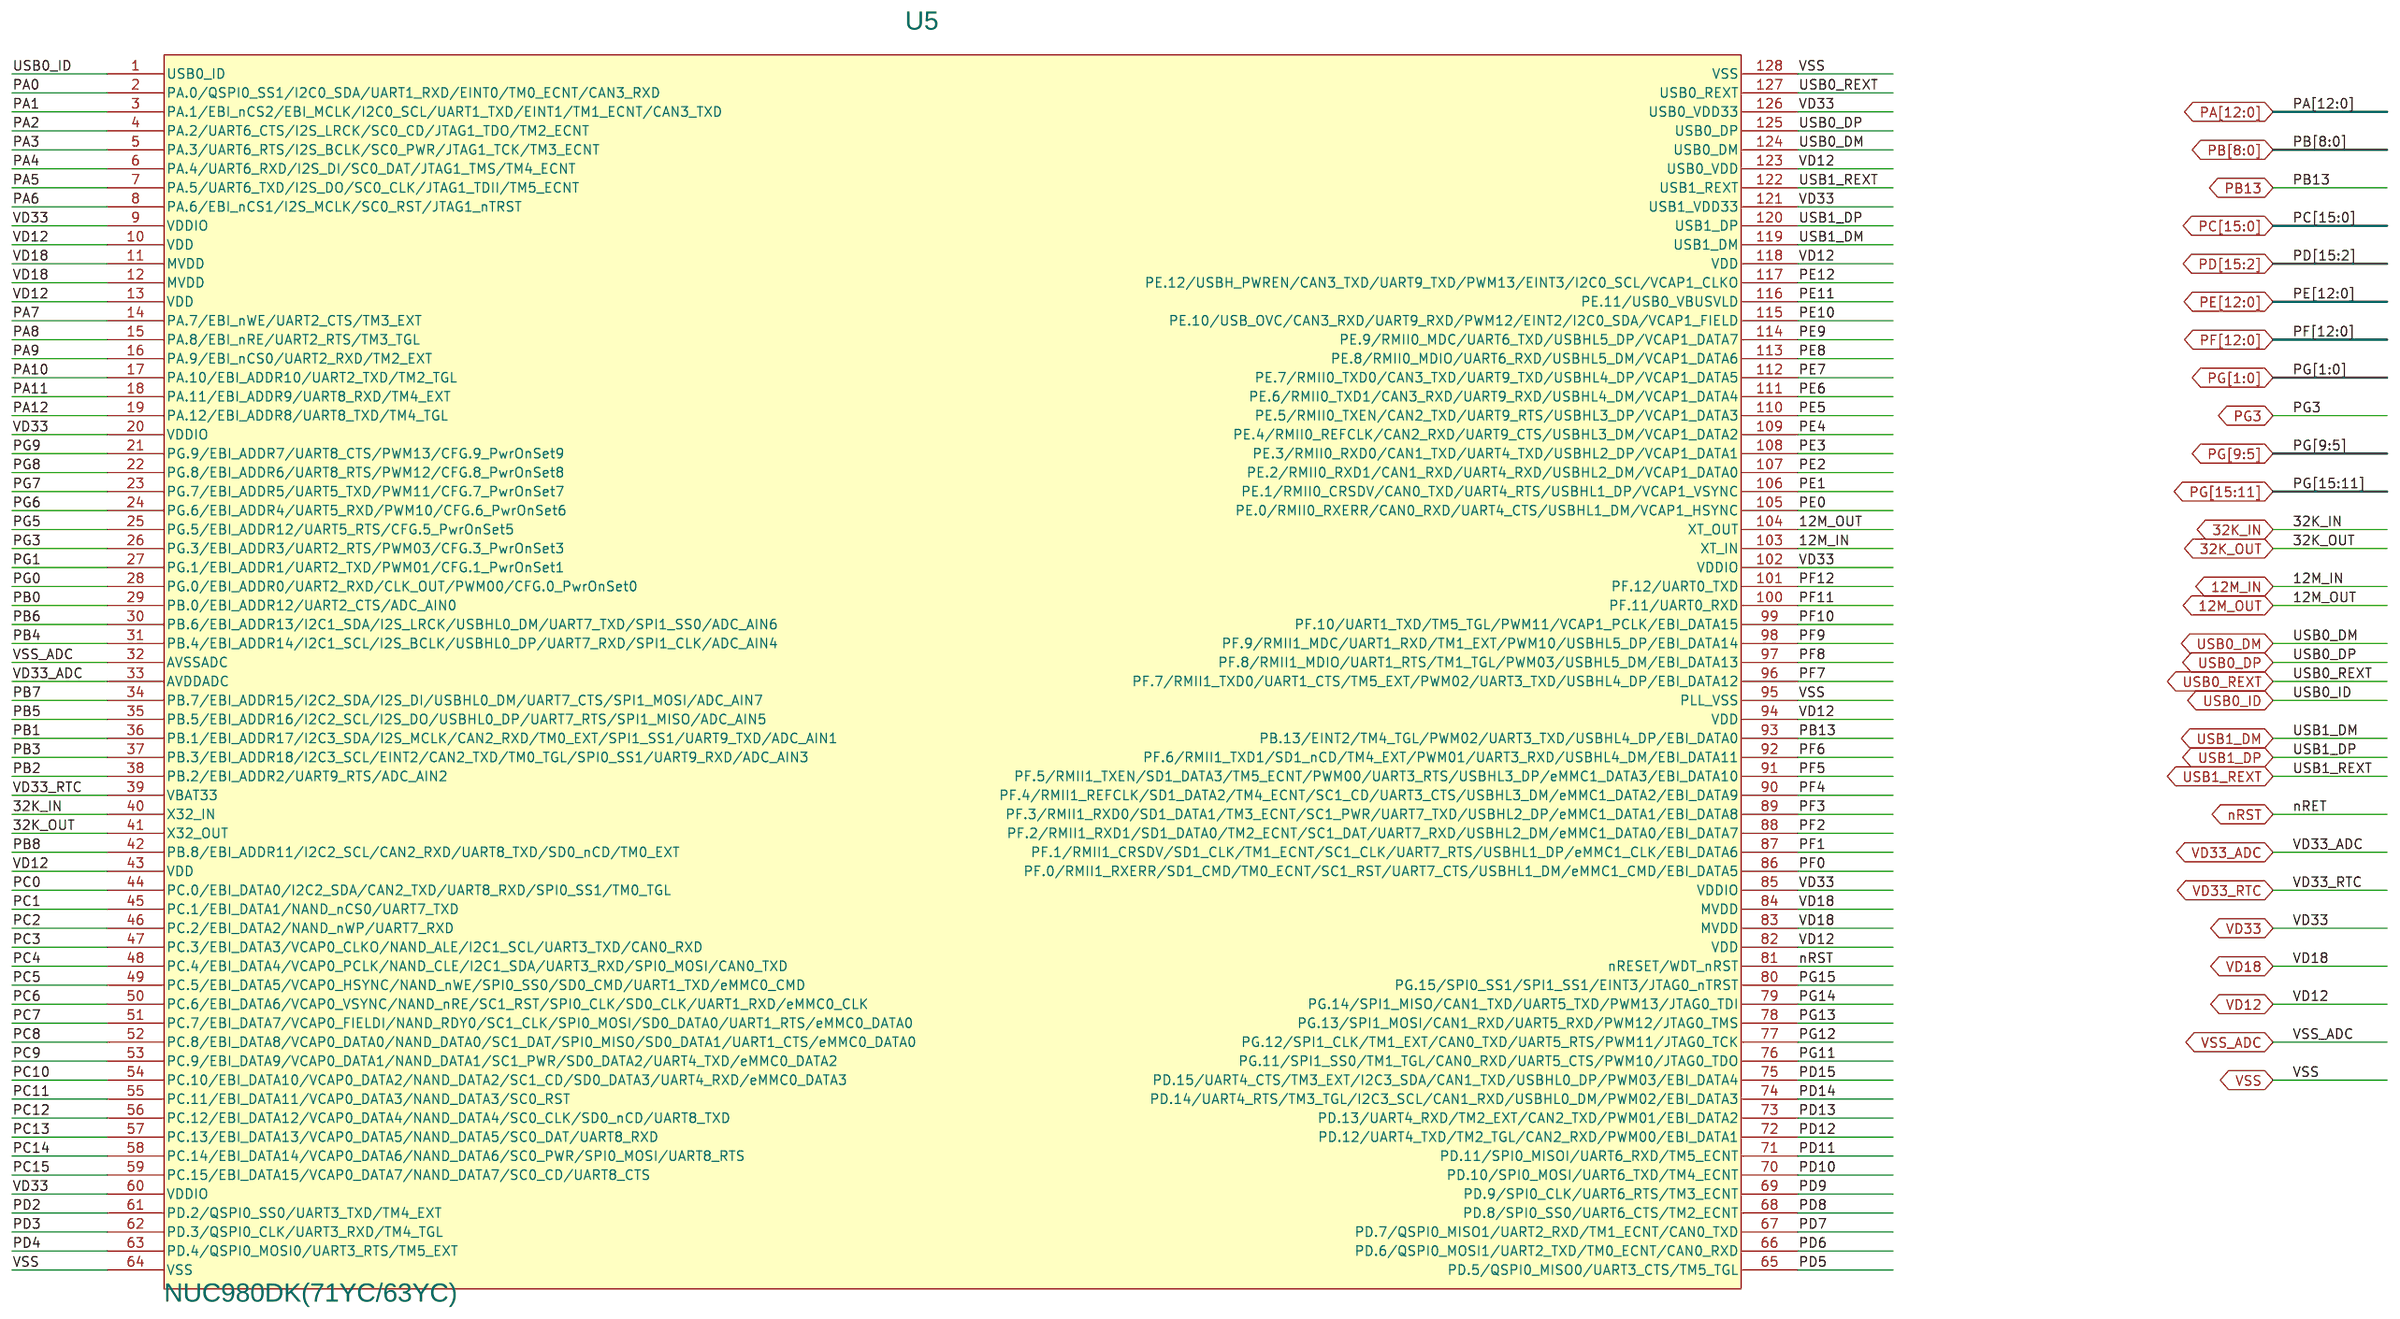
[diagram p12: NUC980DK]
14 NUC123ZD4AN0: size A; note: NUC123ZD4AN0; block Schematic06
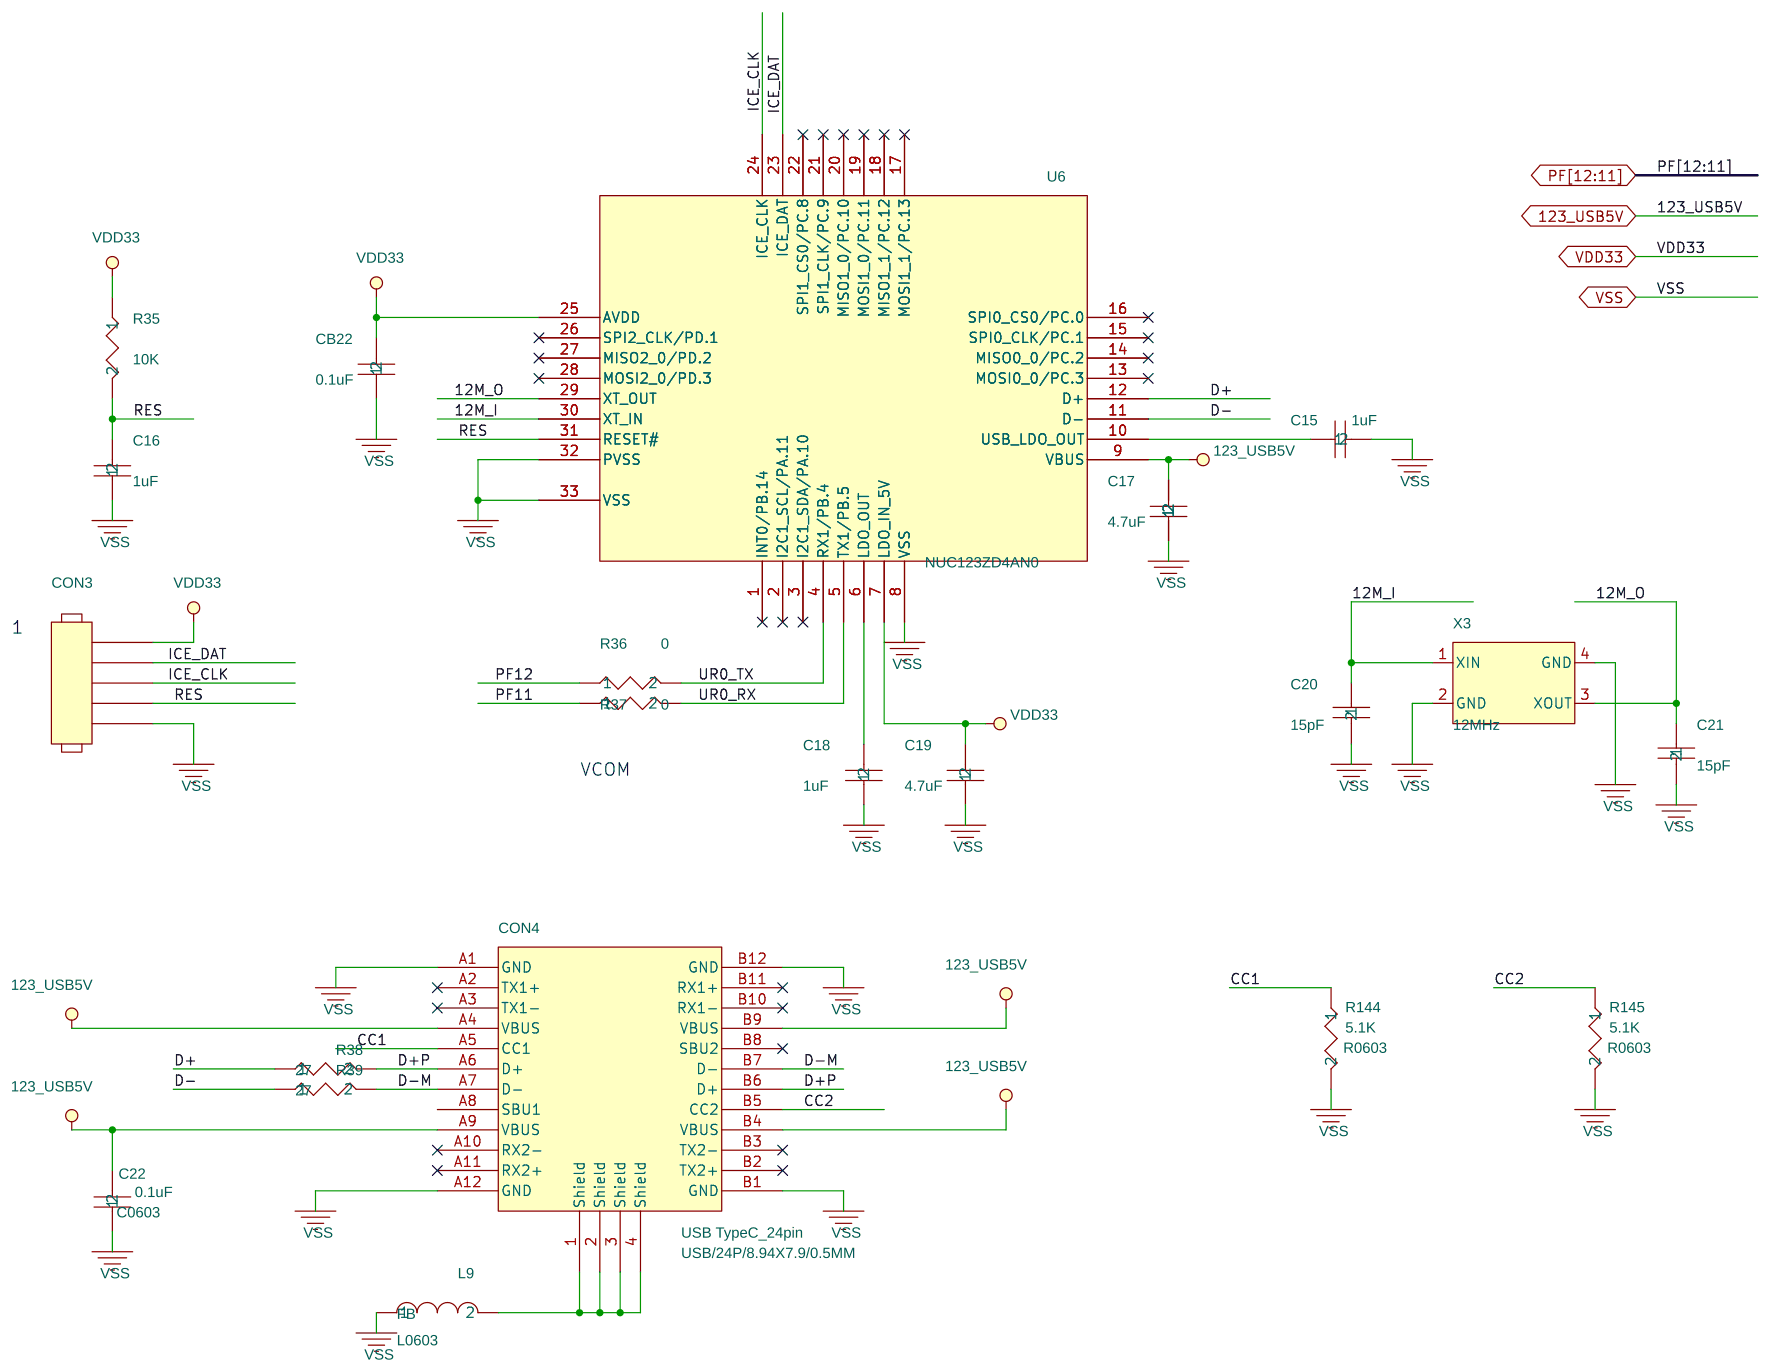
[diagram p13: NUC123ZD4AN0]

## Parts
sheet Arduino Uno
CB34  0.1uF/NC  [C0603]
CB35  0.1uF/NC  [C0603]
CB36  0.1uF/NC  [C0603]
CB37  0.1uF/NC  [C0603]
CB38  0.1uF/NC  [C0603]
CB39  0.1uF/NC  [C0603]
NU1  HEADER 2.54 8X1 female  [SIP-8P]
NU2  HEADER 2.54 10X1 female  [HEADER10X1]
NU3  HEADER 2.54 6X1 female  [SIP-6P]
NU4  HEADER 2.54 8X1 female  [SIP-8P]
NU5  header 2.54 2X4 ¤½(¥¿­±)  [HEADER4X2]
R75  0/NC  [R0603]
R76  0  [R0603]
R77  0  [R0603]
R78  0  [R0603]
R79  0/NC  [R0603]
R80  0/NC  [R0603]
R81  0  [R0603]
R82  0/NC  [R0603]
R83  0/NC  [R0603]
R84  0/NC  [R0603]
R85  0  [R0603]
R86  0  [R0603]
sheet Configure
C12  1nF  [C0603]
C13  1uF  [C0603]
C14  1uF  [C0603]
CB20  0.1uF  [C0603]
CB21  0.1uF  [C0603]
CON12  HEADER10/2.54mm_M  [HEADER10/2.54MM_M]
CON14  HD-351-02P  [SIP/2P_3.5MM]
JP2  HEADER 2x1 (2.54mm, male)  [Header_2x1_2.54mm]
JP3  HEADER3/2.54mm_M
JP4  HEADER3/2.54mm_M
JP5  HEADER3/2.54mm_M
K1  SMD 6X6X5H ¶Â  [STS-B5]
K2  SMD 6X6X5H ¶Â  [STS-B5]
K3  SMD 6X6X5H ¶Â  [STS-B5]
L8  FB  [0603]
LED3  LED_YELLOW  [LED_0805]
LED4  LED_GREEN  [LED_0805]
LED5  LED_RED  [LED_0805]
Q1  2N3904  [SOT-23BEC]
R22  10K  [R0603]
R23  10K  [R0603]
R24  10K  [R0603]
R25  10K  [R0603]
R26  10K/NC  [R0603]
R27  10K  [R0603]
R28  330  [R0603]
R29  330  [R0603]
R30  330  [R0603]
R31  470  [R0603]
R32  100K  [R0603]
R33  0/NC  [R0603]
R34  100K  [R0603]
R136  0  [R0603]
R137  120  [R0603]
R138  0  [R0603]
R139  120  [R0603]
RP1  10K-8P4R  [8P4RA]
SW1  SMD HPS602-E  [SW1X2]
U13  SN65HVD230  [SO-8-1.27X5.4M]
U14  SN65HVD230  [SO-8-1.27X5.4M]
sheet EBI_Connect
CON11  HEADER 14X2(NC)  [HEADER14X2/2.54MM_M]
CON15  HD-351-02P  [SIP/2P_3.5MM]
JP10  HEADER3/2.54mm_M
JP11  HEADER3/2.54mm_M
JP12  HEADER3/2.54mm_M
R135  120  [R0603]
R140  0  [R0603]
U15  SN65HVD230  [SO-8-1.27X5.4M]
sheet I2S, I2C_0
C32  4.7uF  [C0603]
C33  47uF  [CAP_B]
C34  1uF  [C0603]
C35  1uF  [C0603]
C36  100uF/6.3V  [CAP_A]
C37  100uF/6.3V  [CAP_A]
C38  33pF  [C0603]
C39  33pF  [C0603]
C40  1uF  [C0603]
C41  1uF  [C0603]
C42  1uF  [C0603]
C43  1uF  [C0603]
C49  4.7uF  [C0603]
C50  1nF  [C0603]
CB29  0.1uF  [C0603]
CB30  0.1uF  [C0603]
CB31  0.1uF  [C0603]
CB32  0.1uF  [C0603]
CN1  HEADER2X2(NC)  [CONS/2X2/2.54]
CON6  Spko(NC)  [Header_2x1_2.54mm]
CON7  2SJ3080-000111F SMD  [PHONE-PJK-634M_AS]
CT24  10uF  [C0603]
CT25  10uF  [C0603]
CT26  10uF  [C0603]
JP7  HEADER3/2.54mm_M
JP8  HEADER3/2.54mm_M
JP13  HEADER 2x1 (2.54mm, male)  [Header_2x1_2.54mm]
M1  DIP LF-M6027F  [9.7D2.54mm]
R61  0  [R0603]
R62  680  [R0603]
R63  2.2K  [R0603]
R64  2.2K  [R0603]
R65  100K  [R0603]
R66  4.7K  [R0603]
R67  4.7K  [R0603]
R68  33  [R0603]
R69  10K  [R0603]
R70  33  [R0603]
R71  10K  [R0603]
R72  0  [R0603]
R73  0  [R0603]
R98  2.2K  [R0603]
R99  0  [R0603]
R105  NC  [R0603]
R141  0  [R0603]
R142  120  [R0603]
T2  RMICN  [1PAD_1.25x1.25mm]
U11  NAU88C22YG  [QFN32L_5x5mm\0.5mm_pitch]
U16  SN65HVD230  [SO-8-1.27X5.4M]
sheet NUC123ZD4AN0
C15  1uF  [C0603]
C16  1uF  [C0603]
C17  4.7uF  [C0603]
C18  1uF  [C0603]
C19  4.7uF  [C0603]
C20  15pF  [C0603]
C21  15pF  [C0603]
C22  0.1uF  [C0603]
CB22  0.1uF  [C0603]
CON3  HEADER5/2.54mm_M(NC)  [CON/5X1/2.54]
CON4  USB TypeC_24pin  [USB/24P/8.94X7.9/0.5MM]
L9  FB  [L0603]
R35  10K  [R0603]
R36  0  [R0603]
R37  0  [R0603]
R38  27  [R0603]
R39  27  [R0603]
R144  5.1K  [R0603]
R145  5.1K  [R0603]
U6  NUC123ZD4AN0  [QFN33_5X5]
X3  12MHz  [TXC7m-3.2x2.5mm]
sheet NUC980DK
U5  NUC980DK(71YC/63YC)  [LQFP-128]
sheet Power Filter
C8  15pF  [C0603]
C9  15pF  [C0603]
C10  15pF  [C0603]
C11  15pF  [C0603]
CB3  0.1uF  [C0603]
CB4  0.1uF  [C0603]
CB5  0.1uF  [C0603]
CB6  0.1uF  [C0603]
CB7  0.1uF  [C0603]
CB8  0.1uF  [C0603]
CB9  0.1uF  [C0603]
CB10  0.1uF  [C0603]
CB11  0.1uF  [C0603]
CB12  0.1uF  [C0603]
CB13  0.1uF  [C0603]
CB14  0.1uF  [C0603]
CB15  0.1uF  [C0603]
CB16  0.1uF  [C0603]
CB17  0.1uF  [C0603]
CB18  0.1uF  [C0603]
CB19  0.1uF  [C0603]
CT12  10uF  [C0603]
CT13  10uF  [C0603]
CT14  10uF  [C0603]
CT15  10uF  [C0603]
CT16  10uF  [C0603]
CT17  10uF  [C0603]
CT18  10uF  [C0603]
CT19  10uF  [C0603]
L4  FB  [0603]
L5  FB  [0603]
L6  FB  [0603]
L7  FB  [0603]
R18  0  [R0603]
R19  12.1K  [R0603]
R20  12.1K  [R0603]
R21  1M  [R0603]
X1  TXC-9H T9 SMD 32.768KHz 30ppm  [XTAL_2P/1.5mm]
X2  12MHz  [TXC7m-3.2x2.5mm]
sheet Power
C1  1uF  [C0603]
C2  470pF  [C0603]
C3  NC  [C0603]
C4  1nF  [C0603]
C5  NC  [C0603]
C6  1nF  [C0603]
C7  NC  [C0603]
CB1  0.1uF  [C0603]
CB2  0.1uF  [C0603]
CT1  10uF  [C0603]
CT2  10uF  [C0603]
CT3  10uF  [C0603]
CT4  10uF  [C0603]
CT5  10uF  [C0603]
CT6  10uF  [C0603]
CT7  10uF  [C0603]
CT8  10uF  [C0603]
CT9  10uF  [C0603]
CT10  10uF  [C0603]
CT11  10uF  [C0603]
D1  SS24A  [403A-03]
D2  SS24A  [403A-03]
D3  RB521S-30  [SOD-523]
D4  RB521S-30  [SOD-523]
JP14  HEADER2/2.54mm_M  [HEADER2/2.54MM_M]
JP15  HEADER 2x1 (2.54mm, male) (NC)  [HEADER2/2.54MM_M]
L1  NR3015-4R7M-4.7uH  [SMTDR43]
L2  NR3015-4R7M-4.7uH  [SMTDR43]
L3  NR3015-4R7M-4.7uH  [SMTDR43]
LED1  LED_RED  [LED_0805]
LED2  LED_YELLOW  [LED_0805]
R1  100K  [R0603]
R2  10K  [R0603]
R3  15K  [R0603]
R4  10K  [R0603]
R5  2.7K  [R0603]
R6  0  [R0603]
R7  680K  [R0603]
R8  150K  [R0603]
R9  10K  [R0603]
R10  0  [R0603]
R11  200K  [R0603]
R12  100K  [R0603]
R13  1K  [R0603]
R14  10K  [R0603]
R15  0  [R0603]
R16  120K  [R0603]
R17  120K  [R0603]
R100  0  [R0603]
R101  0  [R0603]
R102  0  [R0603]
R103  0(NC)  [R0603]
R104  0(NC)  [R0603]
U1  APL3211AQBI  [TDFN2x2-8]
U2  FP6381AS5CTR  [TSOT-25]
U3  FP6381AS5CTR  [TSOT-25]
U4  FP6381AS5CTR  [TSOT-25]
sheet RMII_PE
C25  NC  [C0603]
C26  30pF  [C0603]
C27  30pF  [C0603]
C28  0.01uF  [C0603]
C29  0.01uF  [C0603]
C30  1000pF/2KV  [C1206]
C31  1000pF/2KV  [C1206]
CB24  0.1uF  [C0603]
CB25  0.1uF  [C0603]
CB26  0.1uF  [C0603]
CB27  0.1uF  [C0603]
CB28  0.1uF  [C0603]
CON5  RJ-45 8P8C_LED R/A  [RJ45\8P\JA\LED]
CT21  10uF  [C0603]
CT22  10uF  [C0603]
CT23  10uF  [C0603]
L10  FB  [L0603]
L11  FB  [L0603]
R45  6.19K  [R0603]
R46  5.1K  [R0603]
R47  5.1K  [R0603]
R48  0  [R0603]
R49  1M  [R0603]
R50  5.1K  [R0603]
R51  330  [R0603]
R52  330  [R0603]
R53  10K  [R0603]
R54  5.1K  [R0603]
R55  10K  [R0603]
R56  5.1K  [R0603]
R57  75  [R0603]
R58  75  [R0603]
R59  75  [R0603]
R60  75  [R0603]
U9  IP101GR  [QFN32]
U10  TS8121C  [ST6200T]
X4  25MHz  [TXC7V-3.2x2.5mm]
sheet SD_Card
C44  NC  [C0603]
CB33  0.1uF  [C0603]
CON8  B8502A-13SB-HPA (T-Flash Card)  [B8502A-13SB-HPA]
CT27  10uF  [C0603]
L13  FB  [0603]
L16  FB  [0603]
R74  0  [R0603]
RR1  10K-8P4R  [8P4RA]
RR2  10K-8P4R  [8P4RA]
sheet SPI Nand Flash
C24  NC  [C0603]
CB23  0.1uF  [C0603]
CT20  10uF  [C0603]
R40  10K  [R0603]
R41  10K  [R0603]
R42  10K  [R0603]
R43  0  [R0603]
R44  10K  [R0603]
U7  W25Q128BV  [SOIC16_300]
U8  W25N01GVZEIG (WSON-8)  [SOIC8_208_EP]
sheet USB
C46  0.1uF  [C0603]
C48  0.01uF  [C0603]
C51  1uF  [C0603]
CB40  0.1uF  [C0603]
CON9  USB TypeC_24pin  [USB/24P/8.94X7.9/0.5MM]
CON10  USB_TYPE-A_RECAP.  [USB4P]
CT28  10uF  [C0603]
CT29  10uF  [C0603]
F2  FUSE(6V/1A)
JP1  HEADER 2x1 (2.54mm, male)  [Header_2x1_2.54mm]
L14  FB  [L0603]
L15  FB  [0603]
Q4  SI2301 (PMOS)  [SOT23-GSD]
Q5  2N3904  [SOT-23BEC]
Q6  SI2301 (PMOS)  [SOT23-GSD]
Q7  SI2301 (PMOS)  [SOT23-GSD]
Q8  SI2304 (NMOS)  [SOT-23]
Q9  SI2304 (NMOS)  [SOT-23]
R87  20K  [R0603]
R88  10K  [R0603]
R90  0  [R0603]
R91  10K  [R0603]
R92  39K  [R0603]
R93  0  [R0603]
R94  0  [R0603]
R95  100K  [R0603]
R96  4.7  [R0603]
R97  4.7  [R0603]
R148  56K  [R0603]
R149  56K  [R0603]
R150  5.1K  [R0603]
R151  5.1K  [R0603]
U12  AP2511M8-13  [MSOP-8]

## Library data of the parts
C9 C21 C24 C29 C35 CB21 CB34 CT1 CT27 CT29 = CAP_NP
C11 C20 C26 C44 CB20 CB23 CB29 CB35 CT3 CT28 = CAP_NP_1
C10 C14 C34 C51 CB24 CB36 CT9 = CAP_NP_3
C28 C38 CB37 CT7 = CAP_NP_5
C2 C8 C12 C32 CB27 CB33 CB38 CB40 CT20 = CAP_NP_2
C7 C13 C48 CB25 CB39 CT25 = CAP_NP_4
NU1 = NuEdu_NU1
NU2 = NuEdu_NU6_2
NU3 = NuEdu_NU2_0
NU4 = NuEdu_NU5_1
NU5 = NuEdu_NU7
R17 R19 R28 R35 R41 R56 R70 R74 R75 R97 = R
R2 R55 R76 R137 = R_10
R7 R27 R54 R77 R142 = R_8
R13 R32 R57 R61 R78 R90 = R_6
R31 R40 R59 R67 R79 R95 R100 = R_4
R10 R18 R44 R48 R80 R88 = R_3
R29 R60 R63 R81 R102 = R_9
R22 R45 R66 R82 R87 R101 = R_7
R16 R24 R49 R68 R83 R91 = R_5
R3 R21 R25 R37 R42 R52 R62 R84 R92 R135 = R_1
R6 R20 R36 R43 R50 R64 R85 R96 = R_2
R33 R46 R86 R104 = R_11
CON12 = HEADER_10
CON14 CON15 JP2 JP13 = HEADER_2
JP3-JP5 JP7 JP8 JP10-JP12 = HEADER_3
K1 = SW-S
K2 = SW-S_1
K3 = SW-S_2
L4 L8 L10 L13 L15 = INDUCTOR
LED3 = LED_0_1
LED4 = LED_0_2
LED5 = LED_0
Q1 Q5 = NPN
R23 R53 R103 = R_15
R1 R26 = R_16
R9 R30 R58 = R_12
R4 R34 R51 = R_13
R136 = R_2: Package: R0402
R138 R141 = R_3: Package: R0402
R12 R47 R139 = R_14
RP1 RR1 RR2 = R-PACK8_0_v2
SW1 = SW_DIP-2_0
U13-U16 = SN65HVD230: Package: SO-8
CON11 = HEADER_12X2_1
R140 = R: Package: R0402
C33 = CAP-T_2
C36 = CAP-T_1
C37 = CAP-T
C5 C27 C39 = CAP_NP_8
C40 C42 = CAPACITOR_NON-POL_3
C41 = CAPACITOR_NON-POL_1
C43 = CAPACITOR_NON-POL_2
C15 C49 = CAP-C_1: Package: 0603
C17 C50 = CAP-C: Package: 0603
CB1 CB28 CB30 = CAP_NP_9
C25 CB31 CT5 = CAP_NP_11
C4 CB32 CT22 = CAP_NP_10
CN1 = HEADER_2X2_0
CON6 JP1 = CON2
CON7 = SJ-435107RS_9: Part Number: CP-435107RS-ND; Vendor: Digikey
C3 CB26 CT24 = CAP_NP_7
CT4 CT23 CT26 = CAP_NP_6
M1 = MICROPHONE_2
R65 R144 R151 = R_0_1: Package: 0603
R69 R149 = R_0_3: Package: 0603
R71 = R_0_5: Package: 0603
R38 R72 R94 = R_33
R39 R73 R93 = R_33_1
R98 R148 = R_0_2: Package: 0603
R99 R145 R150 = R_0: Package: 0603
R105 = R_0_4: Package: 0603
T2 = 1PAD
U11 = NAU8501_0
C16 = CAP-C_4: Package: 0603
C18 = CAP-C_5: Package: 0603
C19 = CAP-C_2: Package: 0603
C22 = CAP-C_6: Package: 0603; element_no: C0004
CB22 = CAP-C_3: Package: 0603
CON3 = HEADER_5
CON4 CON9 = micro_USB_5pin_1
L9 L14 = FERRITE_BEAD
U6 = NUC101_QFN_0
X2 X3 = Crystal_SMD_2
U5 = NUC970_19
CB3 = CAP-B_6
CB4 = CAP-B_14
CB5 = CAP-B_3
CB6 = CAP-B_8
CB7 = CAP-B_12
CB8 = CAP-B_19
CB9 = CAP-B_22
CB10 = CAP-B_15
CB11 = CAP-B_1
CB12 = CAP-B_24
CB13 = CAP-B
CB14 = CAP-B_4
CB15 = CAP-B_11
CB16 = CAP-B_20
CB17 = CAP-B_23
CB18 = CAP-B_16
CB19 = CAP-B_18
CT12 = CAP-B_7
CT13 = CAP-B_13
CT14 = CAP-B_2
CT15 = CAP-B_5
CT16 = CAP-B_9
CT17 = CAP-B_21
CT18 = CAP-B_10
CT19 = CAP-B_17
L5 = INDUCTOR_2
L6 = INDUCTOR_3
L7 L11 L16 = INDUCTOR_1
X1 = MA306_SM_2: Vendor: TXC
C1 CT21 = CAP_NP_12
C6 = CAP_NP_16
CB2 = CAP_NP_15
CT2 = CAP_NP_17
CT6 = CAP_NP_13
CT8 = CAP_NP_14
CT10 = CAP_NP_19
CT11 = CAP_NP_18
D1-D4 = ZENAR_0: Package: D
JP14 JP15 = HEADER_2_v2
L1 = INDUCTOR_IRON_2
L2 = INDUCTOR_IRON_1
L3 = INDUCTOR_IRON
LED1 LED2 = LED
R5 = R_17
R8 = R_19
R11 = R_20
R14 = R_18
R15 = R_21
U1 = APL3203A_1
U2-U4 = ZT7103S_0
C30 = CAP-C: Package: 1206
C31 = CAP-C_1: Package: 1206
CON5 = RJ45_SHLD_0
U9 = IP101GA_2
U10 = PE-68515_1
X4 = Crystal_SMD_2: Vendor: Aurum
CON8 = B8502A-13SB-HPA_(T-Flash_Card)
U7 = W25Q128BV_4
U8 = W55X10_3
C46 = CAP-C: Package: 0603; element_no: C0004
CON10 = USB_type_A_connector
F2 = FUSE
Q4 Q6 Q7 = MOSFET_P_4
Q8 Q9 = MOSFET_N_4
U12 = NCT3520W-H10_1

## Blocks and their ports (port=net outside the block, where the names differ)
Schematic07 = schematic Schematic07, on sheet Block Diagram: VDD33, VSS, PD[7:2]
Schematic09 = schematic Schematic09, on sheet Block Diagram: VDD33, VSS, PA[6:0]
Schematic03 = schematic Schematic03, on sheet Block Diagram: PA[12:0], PB[8:0], PB13, PC[15:0], PD[15:2], PE[12:0], PF[12:0], PG[1:0], PG3, PG[9:5], PG[15:11], VD12, VD18, VD33, VD33_ADC, VD33_RTC, VSS_ADC, VSS, 32K_IN, 32K_OUT, 12M_IN, 12M_OUT, USB0_DM, USB0_DP, USB0_REXT, USB0_ID, USB1_DP, USB1_DM, USB1_REXT, nRST
Schematic04 = schematic Schematic04, on sheet Block Diagram: 32K_IN, VDD12, VDD33, VSS_ADC, 32K_OUT, 12M_IN, 12M_OUT, VDD18, VD12, VD18, VD33, VD33_ADC, VSS, USB0_REXT, USB1_REXT
Schematic05 = schematic Schematic05, on sheet Block Diagram: nRESET, VDD12, VDD33, VSS, PG5, PF[12:11], PG[1:0], PG3, PG[9:8], PG[15:11], nRST, PE10, PE12, PB8, PG15, PB13, CAN2_TXD
Schematic01 = schematic Schematic01, on sheet Block Diagram: no ports
Schematic02 = schematic Schematic02, on sheet Block Diagram: VDD12, VSS, VDD18, VDD33, VD33_RTC, VIN, 123_USB5V, 980_USB5V
Schematic11 = schematic SCHEMATIC11, on sheet Block Diagram: PG[14:11], PD[15:8], PB[7:0], PF[10:7], nRESET, VDD33, VSS, PG[7:6], VD33_ADC, VIN, VSS_ADC
Schematic13 = schematic Schematic13, on sheet Block Diagram: PC[15:0], VDD33, VSS, PA[12:7], PB2, PB0, PB4, PB6, CAN2_TXD
Schematic10 = schematic SCHEMATIC10, on sheet Block Diagram: PF[6:0], VSS, VDD33
Schematic12 = schematic Schematic12, on sheet Block Diagram: 980_USB5V, PE11, VDD33, VSS, USB0_DP, USB0_DM, USB1_DP, USB1_DM, VIN, USB0_ID
Schematic06 = schematic Schematic06, on sheet Block Diagram: PF[12:11], VDD33, VSS, 123_USB5V
Schematic08 = schematic Schematic08, on sheet Block Diagram: PE[9:0], VDD33, VSS, nRESET

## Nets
5VIN: C1.1 CT2.2 D1.2(1) D2.2(1) JP14.1 R1.2 R5.2 R103.1 R104.1 U1.1(Vin)
VDD12: C13.2 CT10.1 L6.1 R102.2
VDD18: CT7.1 L7.1 R101.2
VDD33: C19.2 CB22.2 CB23.1 CB29.1 CB30.1 CB33.1 CON3.1 CON8.4(VDD) CON11.27 CON12.1 CT4.1 CT20.1 CT24.1 CT25.1 CT27.1 D3.1(2) L4.1 L10.1 L11.1 NU1.2(VDD) NU1.4(3VCC) NU5.2(VCC) R13.2 R28.2 R29.2 R30.2 R32.1 R35.1 R40.2 R41.2 R42.2 R44.1 R61.2 R65.2 R66.1 R67.1 R88.2 R91.2 R100.2 R105.1 RP1.1(R1) RP1.3(R2) RP1.5(R3) RR1.2(R1) RR1.4(R2) RR1.6(R3) RR1.8(R4) RR2.2(R1) RR2.4(R2) RR2.6(R3) RR2.8(R4) U6.7(LDO_IN_5V) U6.25(AVDD) U7.2(VCC) U8.8(VCC) U11.13(VDDC) U11.14(VDDB) U11.31(VDDA) U13.3(VCC) U14.3(VCC) U15.3(VCC) U16.3(VCC)
VIN: C51.2 CB1.1 CT1.1 CT3.1 CT6.1 CT9.1 F2.2 NU1.5(5VCC) NU1.8(VIN) R4.2 R6.1 R9.2 R10.1 R14.2 R15.1 R103.2 R104.2 U1.8(Vout) U12.2(Vin) U12.3(Vin)
VSS: C1.2 C3.2 C5.2 C7.2 C8.2 C9.2 C10.2 C11.2 C12.1 C14.1 C15.2 C16.1 C17.1 C18.1 C19.1 C20.2 C21.2 C22.1 C24.2 C25.2 C26.2 C27.2 C28.2 C29.2 C31.2 C32.1 C33.2 C38.1 C39.1 C44.2 C46.1 C48.2 C50.2 C51.1 CB1.2 CB2.2 CB3.2 CB4.2 CB5.2 CB6.2 CB7.2 CB8.2 CB9.2 CB11.2 CB12.2 CB13.2 CB14.2 CB15.2 CB16.2 CB17.2 CB18.2 CB19.2 CB20.2 CB21.2 CB22.1 CB23.2 CB24.1 CB25.1 CB26.1 CB27.2 CB28.2 CB29.2 CB30.2 CB31.2 CB32.1 CB33.2 CB40.1 CON3.5 CON4.A1(GND) CON4.A12(GND) CON4.B1(GND) CON4.B12(GND) CON5.11(LED-) CON9.A1(GND) CON9.A12(GND) CON9.B1(GND) CON9.B12(GND) CON11.28 CON12.10 CT1.2 CT2.1 CT3.2 CT4.2 CT5.2 CT6.2 CT7.2 CT8.2 CT9.2 CT10.2 CT11.2 CT12.2 CT14.2 CT15.2 CT16.2 CT17.2 CT18.2 CT19.2 CT20.2 CT21.2 CT22.2 CT23.2 CT24.2 CT25.2 CT26.2 CT27.2 CT28.1 CT29.1 JP1.2 JP14.2 JP15.2 K1.2 K2.2 K3.2 L9.1 L13.1 L14.1 L15.1 L16.2 LED2.2(CATHODE) NU1.6(VSS) NU1.7(VSS) NU2.7(VSS) NU5.6(GND) Q1.EMITTER Q5.EMITTER R1.1 R2.2 R3.2 R8.1 R12.2 R17.2 R18.1 R19.2 R20.2 R22.1 R23.1 R24.1 R25.1 R26.1 R27.1 R34.2 R45.1 R54.2 R56.1 R64.1 R69.1 R71.2 R72.1 R73.1 R92.1 R99.2 R136.2 R138.2 R140.2 R141.2 R144.2 R145.2 R150.2 R151.2 RP1.7(R4) U1.2(GND) U1.9(GND) U2.2(GND) U3.2(GND) U4.2(GND) U5.64(VSS) U5.95(PLL_VSS) U5.128(VSS) U6.8(VSS) U6.32(PVSS) U6.33(VSS) U7.10(GND) U8.4(GND) U8.9(G) U9.33(EPad) U11.12(VSSD) U11.18(MODE) U11.24(VSSSPK) U11.28(VSSA) U11.33(EPAD) U12.1(GND) U13.2(GND) U14.2(GND) U15.2(GND) U16.2(GND) X2.2(GND) X2.4(GND) X3.2(GND) X3.4(GND) X4.2(GND) X4.4(GND)
VSS_ADC: CB10.2 CB34.2 CB35.2 CB36.2 CB37.2 CB38.2 CB39.2 CT13.2 R18.2 U5.32(AVSSADC)
12M_IN: C10.1 R21.2 U5.103(XT_IN) X2.1(XIN)
12M_OUT: C11.1 R21.1 U5.104(XT_OUT) X2.3(XOUT)
32K_IN: C8.1 U5.40(X32_IN) X1.2
32K_OUT: C9.1 U5.41(X32_OUT) X1.1
123_USB5V: C17.2 C22.2 CON4.A4(VBUS) CON4.A9(VBUS) CON4.B4(VBUS) CON4.B9(VBUS) D2.1(2) U6.9(VBUS)
980_USB5V: C46.2 CB40.2 CON9.A4(VBUS) CON9.A9(VBUS) CON9.B4(VBUS) CON9.B9(VBUS) CT29.2 D1.1(2) Q4.2(S) R148.1 R149.1 U12.6(Vout) U12.7(Vout) U12.8(Vout)
CAN2_TXD: JP12.3 U13.1(D)
nRESET: C14.2 K3.3 NU1.3(MCU_RESET) Q1.COLLECTOR R31.1 R32.2 R33.1 U9.32(nRst)
nRST: L8.2 U5.81(nRESET/WDT_nRST)
PA0: JP7.2 U5.2(PA.0/QSPI0_SS1/I2C0_SDA/UART1_RXD/EINT0/TM0_ECNT/CAN3_RXD)
PA1: JP8.2 U5.3(PA.1/EBI_nCS2/EBI_MCLK/I2C0_SCL/UART1_TXD/EINT1/TM1_ECNT/CAN3_TXD)
PA2: U5.4(PA.2/UART6_CTS/I2S_LRCK/SC0_CD/JTAG1_TDO/TM2_ECNT) U11.7(FS)
PA3: U5.5(PA.3/UART6_RTS/I2S_BCLK/SC0_PWR/JTAG1_TCK/TM3_ECNT) U11.8(BCLK)
PA4: U5.6(PA.4/UART6_RXD/I2S_DI/SC0_DAT/JTAG1_TMS/TM4_ECNT) U11.9(ADCOUT)
PA5: U5.7(PA.5/UART6_TXD/I2S_DO/SC0_CLK/JTAG1_TDII/TM5_ECNT) U11.10(DACIN)
PA6: U5.8(PA.6/EBI_nCS1/I2S_MCLK/SC0_RST/JTAG1_nTRST) U11.11(MCLK)
PA7: CON11.17 U5.14(PA.7/EBI_nWE/UART2_CTS/TM3_EXT)
PA8: CON11.18 U5.15(PA.8/EBI_nRE/UART2_RTS/TM3_TGL)
PA9: CON11.19 U5.16(PA.9/EBI_nCS0/UART2_RXD/TM2_EXT)
PA10: CON11.22 U5.17(PA.10/EBI_ADDR10/UART2_TXD/TM2_TGL)
PA11: CON11.21 U5.18(PA.11/EBI_ADDR9/UART8_RXD/TM4_EXT)
PA12: CON11.20 U5.19(PA.12/EBI_ADDR8/UART8_TXD/TM4_TGL)
PB0: CB34.1 CON11.23 NU3.4(ADC3) U5.29(PB.0/EBI_ADDR12/UART2_CTS/ADC_AIN0)
PB1: CB35.1 NU3.1(ADC0) U5.36(PB.1/EBI_ADDR17/I2C3_SDA/I2S_MCLK/CAN2_RXD/TM0_EXT/SPI1_SS1/UART9_TXD/ADC_AIN1)
PB2: CB36.1 CON11.24 NU3.3(ADC2) U5.38(PB.2/EBI_ADDR2/UART9_RTS/ADC_AIN2)
PB3: CB37.1 NU3.2(ADC1) U5.37(PB.3/EBI_ADDR18/I2C3_SCL/EINT2/CAN2_TXD/TM0_TGL/SPI0_SS1/UART9_RXD/ADC_AIN3)
PB4: CB38.1 CON11.25 R75.1 R81.2 U5.31(PB.4/EBI_ADDR14/I2C1_SCL/I2S_BCLK/USBHL0_DP/UART7_RXD/SPI1_CLK/ADC_AIN4)
PB5: NU2.10(I2C1_SCL) U5.35(PB.5/EBI_ADDR16/I2C2_SCL/I2S_DO/USBHL0_DP/UART7_RTS/SPI1_MISO/ADC_AIN5)
PB6: CB39.1 CON11.26 R78.1 R84.1 U5.30(PB.6/EBI_ADDR13/I2C1_SDA/I2S_LRCK/USBHL0_DM/UART7_TXD/SPI1_SS0/ADC_AIN6)
PB7: NU2.9(I2C1_SDA) U5.34(PB.7/EBI_ADDR15/I2C2_SDA/I2S_DI/USBHL0_DM/UART7_CTS/SPI1_MOSI/ADC_AIN7)
PB8: JP3.2 U5.42(PB.8/EBI_ADDR11/I2C2_SCL/CAN2_RXD/UART8_TXD/SD0_nCD/TM0_EXT)
PB13: LED5.2 U5.93(PB.13/EINT2/TM4_TGL/PWM02/UART3_TXD/USBHL4_DP/EBI_DATA0)
PC0: JP12.2 U5.44(PC.0/EBI_DATA0/I2C2_SDA/CAN2_TXD/UART8_RXD/SPI0_SS1/TM0_TGL)
PC1: CON11.2 U5.45(PC.1/EBI_DATA1/NAND_nCS0/UART7_TXD)
PC2: CON11.3 U5.46(PC.2/EBI_DATA2/NAND_nWP/UART7_RXD)
PC3: JP10.2 U5.47(PC.3/EBI_DATA3/VCAP0_CLKO/NAND_ALE/I2C1_SCL/UART3_TXD/CAN0_RXD)
PC4: JP11.2 U5.48(PC.4/EBI_DATA4/VCAP0_PCLK/NAND_CLE/I2C1_SDA/UART3_RXD/SPI0_MOSI/CAN0_TXD)
PC5: CON11.6 U5.49(PC.5/EBI_DATA5/VCAP0_HSYNC/NAND_nWE/SPI0_SS0/SD0_CMD/UART1_TXD/eMMC0_CMD)
PC6: CON11.7 U5.50(PC.6/EBI_DATA6/VCAP0_VSYNC/NAND_nRE/SC1_RST/SPI0_CLK/SD0_CLK/UART1_RXD/eMMC0_CLK)
PC7: CON11.8 U5.51(PC.7/EBI_DATA7/VCAP0_FIELDI/NAND_RDY0/SC1_CLK/SPI0_MOSI/SD0_DATA0/UART1_RTS/eMMC0_DATA0)
PC8: CON11.9 U5.52(PC.8/EBI_DATA8/VCAP0_DATA0/NAND_DATA0/SC1_DAT/SPI0_MISO/SD0_DATA1/UART1_CTS/eMMC0_DATA0)
PC9: CON11.10 U5.53(PC.9/EBI_DATA9/VCAP0_DATA1/NAND_DATA1/SC1_PWR/SD0_DATA2/UART4_TXD/eMMC0_DATA2)
PC10: CON11.11 U5.54(PC.10/EBI_DATA10/VCAP0_DATA2/NAND_DATA2/SC1_CD/SD0_DATA3/UART4_RXD/eMMC0_DATA3)
PC11: CON11.12 U5.55(PC.11/EBI_DATA11/VCAP0_DATA3/NAND_DATA3/SC0_RST)
PC12: CON11.13 U5.56(PC.12/EBI_DATA12/VCAP0_DATA4/NAND_DATA4/SC0_CLK/SD0_nCD/UART8_TXD)
PC13: CON11.14 U5.57(PC.13/EBI_DATA13/VCAP0_DATA5/NAND_DATA5/SC0_DAT/UART8_RXD)
PC14: CON11.15 U5.58(PC.14/EBI_DATA14/VCAP0_DATA6/NAND_DATA6/SC0_PWR/SPI0_MOSI/UART8_RTS)
PC15: CON11.16 U5.59(PC.15/EBI_DATA15/VCAP0_DATA7/NAND_DATA7/SC0_CD/UART8_CTS)
PD2: R42.1 U5.61(PD.2/QSPI0_SS0/UART3_TXD/TM4_EXT) U7.7(CS) U8.1(/CS)
PD3: R43.2 U5.62(PD.3/QSPI0_CLK/UART3_RXD/TM4_TGL)
PD4: U5.63(PD.4/QSPI0_MOSI0/UART3_RTS/TM5_EXT) U7.15(Di/D0) U8.5(Di/D0)
PD5: U5.65(PD.5/QSPI0_MISO0/UART3_CTS/TM5_TGL) U7.8(Do/D1) U8.2(Do/D1)
PD6: R40.1 U5.66(PD.6/QSPI0_MOSI1/UART2_TXD/TM0_ECNT/CAN0_RXD) U7.9(Wp/D2) U8.3(Wp/D2)
PD7: R41.1 U5.67(PD.7/QSPI0_MISO1/UART2_RXD/TM1_ECNT/CAN0_TXD) U7.1(Hld/D3) U8.7(Hld/D3)
PD8: NU5.7(SPI0_SS) U5.68(PD.8/SPI0_SS0/UART6_CTS/TM2_ECNT)
PD9: NU5.3(SPI0_CLK) U5.69(PD.9/SPI0_CLK/UART6_RTS/TM3_ECNT)
PD10: NU5.4(SPI0_MOSI) U5.70(PD.10/SPI0_MOSI/UART6_TXD/TM4_ECNT)
PD11: NU5.1(SPI0_MISO) U5.71(PD.11/SPI0_MISOI/UART6_RXD/TM5_ECNT)
PD12: R76.1 R82.2 U5.72(PD.12/UART4_TXD/TM2_TGL/CAN2_RXD/PWM00/EBI_DATA1)
PD13: R79.1 R85.1 U5.73(PD.13/UART4_RXD/TM2_EXT/CAN2_TXD/PWM01/EBI_DATA2)
PD14: NU4.6(D5) U5.74(PD.14/UART4_RTS/TM3_TGL/I2C3_SCL/CAN1_RXD/USBHL0_DM/PWM02/EBI_DATA3)
PD15: NU4.5(D4) U5.75(PD.15/UART4_CTS/TM3_EXT/I2C3_SDA/CAN1_TXD/USBHL0_DP/PWM03/EBI_DATA4)
PE0: R47.2 U5.105(PE.0/RMII0_RXERR/CAN0_RXD/UART4_CTS/USBHL1_DM/VCAP1_HSYNC) U9.21(RxEr/Int32)
PE1: R56.2 U5.106(PE.1/RMII0_CRSDV/CAN0_TXD/UART4_RTS/USBHL1_DP/VCAP1_VSYNC) U9.19(RxDV/CRS_DV)
PE2: U5.107(PE.2/RMII0_RXD1/CAN1_RXD/UART4_RXD/USBHL2_DM/VCAP1_DATA0) U9.17(RxD1)
PE3: U5.108(PE.3/RMII0_RXD0/CAN1_TXD/UART4_TXD/USBHL2_DP/VCAP1_DATA1) U9.18(RxD0)
PE4: R48.1 U5.109(PE.4/RMII0_REFCLK/CAN2_RXD/UART9_CTS/USBHL3_DM/VCAP1_DATA2) U9.14(RxClk/50M_Clko)
PE5: U5.110(PE.5/RMII0_TXEN/CAN2_TXD/UART9_RTS/USBHL3_DP/VCAP1_DATA3) U9.5(TxEn)
PE6: U5.111(PE.6/RMII0_TXD1/CAN3_RXD/UART9_RXD/USBHL4_DM/VCAP1_DATA4) U9.8(TxD1)
PE7: U5.112(PE.7/RMII0_TXD0/CAN3_TXD/UART9_TXD/USBHL4_DP/VCAP1_DATA5) U9.9(TxD0)
PE8: R46.2 U5.113(PE.8/RMII0_MDIO/UART6_RXD/USBHL5_DM/VCAP1_DATA6) U9.23(MDIO)
PE9: U5.114(PE.9/RMII0_MDC/UART6_TXD/USBHL5_DP/VCAP1_DATA7) U9.22(MDC)
PE10: CB20.1 K1.4 U5.115(PE.10/USB_OVC/CAN3_RXD/UART9_RXD/PWM12/EINT2/I2C0_SDA/VCAP1_FIELD)
PE11: R87.1 R92.2 U5.116(PE.11/USB0_VBUSVLD)
PE12: CB21.1 K2.4 U5.117(PE.12/USBH_PWREN/CAN3_TXD/UART9_TXD/PWM13/EINT3/I2C0_SCL/VCAP1_CLKO)
PF0: CON8.3(CMD) RR2.5(R3) U5.86(PF.0/RMII1_RXERR/SD1_CMD/TM0_ECNT/SC1_RST/UART7_CTS/USBHL1_DM/eMMC1_CMD/EBI_DATA5)
PF1: R74.2 U5.87(PF.1/RMII1_CRSDV/SD1_CLK/TM1_ECNT/SC1_CLK/UART7_RTS/USBHL1_DP/eMMC1_CLK/EBI_DATA6)
PF2: CON8.7(DAT0) RR1.1(R1) U5.88(PF.2/RMII1_RXD1/SD1_DATA0/TM2_ECNT/SC1_DAT/UART7_RXD/USBHL2_DM/eMMC1_DATA0/EBI_DATA7)
PF3: CON8.8(DAT1) RR1.3(R2) U5.89(PF.3/RMII1_RXD0/SD1_DATA1/TM3_ECNT/SC1_PWR/UART7_TXD/USBHL2_DP/eMMC1_DATA1/EBI_DATA8)
PF4: CON8.1(DAT2) RR2.1(R1) U5.90(PF.4/RMII1_REFCLK/SD1_DATA2/TM4_ECNT/SC1_CD/UART3_CTS/USBHL3_DM/eMMC1_DATA2/EBI_DATA9)
PF5: CON8.2(DAT3) RR2.3(R2) U5.91(PF.5/RMII1_TXEN/SD1_DATA3/TM5_ECNT/PWM00/UART3_RTS/USBHL3_DP/eMMC1_DATA3/EBI_DATA10)
PF6: CON8.9(CD) RR1.5(R3) U5.92(PF.6/RMII1_TXD1/SD1_nCD/TM4_EXT/PWM01/UART3_RXD/USBHL4_DM/EBI_DATA11)
PF7: NU2.1(D8) U5.96(PF.7/RMII1_TXD0/UART1_CTS/TM5_EXT/PWM02/UART3_TXD/USBHL4_DP/EBI_DATA12)
PF8: NU2.2(D9) U5.97(PF.8/RMII1_MDIO/UART1_RTS/TM1_TGL/PWM03/USBHL5_DM/EBI_DATA13)
PF9: NU4.1(D0/RX1) U5.98(PF.9/RMII1_MDC/UART1_RXD/TM1_EXT/PWM10/USBHL5_DP/EBI_DATA14)
PF10: NU4.2(D1/TX1) U5.99(PF.10/UART1_TXD/TM5_TGL/PWM11/VCAP1_PCLK/EBI_DATA15)
PF11: CON12.9 R37.1 U5.100(PF.11/UART0_RXD)
PF12: CON12.8 R36.1 U5.101(PF.12/UART0_TXD)
PG0: SW1.1(A1) U5.28(PG.0/EBI_ADDR0/UART2_RXD/CLK_OUT/PWM00/CFG.0_PwrOnSet0)
PG1: SW1.2(A2) U5.27(PG.1/EBI_ADDR1/UART2_TXD/PWM01/CFG.1_PwrOnSet1)
PG3: R24.2 U5.26(PG.3/EBI_ADDR3/UART2_RTS/PWM03/CFG.3_PwrOnSet3)
PG5: R25.2 U5.25(PG.5/EBI_ADDR12/UART5_RTS/CFG.5_PwrOnSet5)
PG6: NU4.7(D6) U5.24(PG.6/EBI_ADDR4/UART5_RXD/PWM10/CFG.6_PwrOnSet6)
PG7: NU4.8(D7) U5.23(PG.7/EBI_ADDR5/UART5_TXD/PWM11/CFG.7_PwrOnSet7)
PG8: R26.2 U5.22(PG.8/EBI_ADDR6/UART8_RTS/PWM12/CFG.8_PwrOnSet8)
PG9: R27.2 U5.21(PG.9/EBI_ADDR7/UART8_CTS/PWM13/CFG.9_PwrOnSet9)
PG11: CON12.6 NU2.3(D10/PWM0) U5.76(PG.11/SPI1_SS0/TM1_TGL/CAN0_RXD/UART5_CTS/PWM10/JTAG0_TDO)
PG12: CON12.5 NU2.6(D13/PWM3) RP1.8(R4) U5.77(PG.12/SPI1_CLK/TM1_EXT/CAN0_TXD/UART5_RTS/PWM11/JTAG0_TCK)
PG13: JP4.2 R80.1 R86.1 U5.78(PG.13/SPI1_MOSI/CAN1_RXD/UART5_RXD/PWM12/JTAG0_TMS)
PG14: JP5.2 R77.1 R83.2 U5.79(PG.14/SPI1_MISO/CAN1_TXD/UART5_TXD/PWM13/JTAG0_TDI)
PG15: CON12.2 LED4.2 RP1.2(R1) U5.80(PG.15/SPI0_SS1/SPI1_SS1/EINT3/JTAG0_nTRST)
PHY_AVDD33: CB26.2 CT23.1 L11.2 U9.31(AVD33)
PHY_DVDD33: CB25.2 CON5.10(LED+) CT22.1 L10.2 R46.1 R47.1 R50.1 R53.2 R55.2 U9.13(IOVDD)
Schematic05/CAN1_H: CON14.1 R139.1 U14.7(CANH)
Schematic05/CAN1_L: CON14.2 R139.2 U14.6(CANL)
Schematic05/CAN1_RS: R138.1 U14.8(Rs)
Schematic05/CAN1_RXD: JP4.3 U14.4(R)
Schematic05/CAN1_TXD: JP5.3 U14.1(D)
Schematic05/CAN2_H: JP2.1 R137.1 U13.7(CANH)
Schematic05/CAN2_L: JP2.2 R137.2 U13.6(CANL)
Schematic05/CAN2_RS: R136.1 U13.8(Rs)
Schematic05/CAN2_RXD: JP3.3 U13.4(R)
Schematic05/LED_YELLOW: JP3.1 LED3.2
Schematic05/TDI: CON12.3 JP5.1 RP1.4(R2)
Schematic05/TMS: CON12.4 JP4.1 RP1.6(R3)
Schematic06/12M_I: C20.1 U6.30(XT_IN) X3.1(XIN)
Schematic06/12M_O: C21.1 U6.29(XT_OUT) X3.3(XOUT)
Schematic06/CC1: CON4.A5(CC1) R144.1
Schematic06/CC2: CON4.B5(CC2) R145.1
Schematic06/D+: R38.1 U6.12(D+)
Schematic06/D+P: CON4.A6(D+) CON4.B6(D+) R38.2
Schematic06/D-: R39.1 U6.11(D-)
Schematic06/D-M: CON4.A7(D-) CON4.B7(D-) R39.2
Schematic06/ICE_CLK: CON3.3 U6.24(ICE_CLK)
Schematic06/ICE_DAT: CON3.2 U6.23(ICE_DAT)
Schematic06/RES: C16.2 CON3.4 R35.2 U6.31(RESET#)
Schematic06/UR0_RX: R37.2 U6.5(TX1/PB.5)
Schematic06/UR0_TX: R36.2 U6.4(RX1/PB.4)
Schematic07/CLK: C24.1 R43.1 U7.16(CLK) U8.6(CLK)
Schematic08/E_COL: R53.1 U9.4(Col/RMII)
Schematic08/E_CRS: R55.1 U9.20(CRS/LEDMod)
Schematic08/E_ETH_XI: C26.1 R49.2 U9.2(Xi) X4.1(XIN)
Schematic08/E_ETH_XO: C27.1 R49.1 U9.3(Xo) X4.3(XOUT)
Schematic08/E_MDI_RN: U9.26(MDiRn) U10.8(RD-)
Schematic08/E_MDI_RP: U9.27(MDiRp) U10.6(RD+)
Schematic08/E_MDI_TN: U9.29(MDiTn) U10.3(TD-)
Schematic08/E_MDI_TP: U9.30(MDiTp) U10.1(TD+)
Schematic08/E_PHY_AD0: R50.2 R52.1 U9.11(LED0/PhyAD0)
Schematic08/E_PHY_AD3: R51.1 R54.1 U9.12(LED3/PhyAD3)
Schematic08/E_REG_OUT: CB24.2 CT21.1 U9.28(RegOut)
Schematic08/E_RX+: CON5.3(RX+) U10.11(RX+)
Schematic08/E_RX-: CON5.6(RX-) U10.9(RX-)
Schematic08/E_RX_CLK: C25.1 R48.2 U9.10(TxClk/50MClki)
Schematic08/E_TX+: CON5.1(TX+) U10.16(TX+)
Schematic08/E_TX-: CON5.2(TX-) U10.14(TX-)
Schematic09/AUXO1: C42.2 CN1.1 R73.2
Schematic09/AUXO2: C40.2 CN1.2 R72.2
Schematic09/AUXOUT1: C42.1 U11.21(AUXOUT1)
Schematic09/AUXOUT2: C40.1 U11.22(AUXOUT2)
Schematic09/CAN3_H: JP13.1 R142.1 U16.7(CANH)
Schematic09/CAN3_L: JP13.2 R142.2 U16.6(CANL)
Schematic09/CAN3_RS: R141.1 U16.8(Rs)
Schematic09/CAN3_RXD: JP7.3 U16.4(R)
Schematic09/CAN3_TXD: JP8.3 U16.1(D)
Schematic09/GPIO2: CON7.5(DETECT) R65.1 U11.3(LLIN/GPIO2)
Schematic09/I2S_I2C_SCL: C39.2 R68.1 U11.16(SCLK)
Schematic09/I2S_I2C_SDA: C38.2 R70.1 U11.17(SDIO)
Schematic09/LAUXI: C43.2 CN1.4
Schematic09/LAUXIN: C43.1 U11.19(LAUXIN)
Schematic09/LHP: C37.1 U11.30(LHP)
Schematic09/LSPKOUT: CON6.2 U11.25(LSP_O)
Schematic09/MIC_BIAS: C33.1 CB32.2 R62.2 R63.2 R98.1 R105.2
Schematic09/MICN: C34.1 U11.2(LMICN)
Schematic09/MICP: C35.1 U11.1(LMICP)
Schematic09/N65: C37.2 CON7.1(LEFT) R71.1
Schematic09/N66: C36.2 CON7.2(RIGHT) R69.2
Schematic09/N67: C49.1 C50.1 CON7.4(M/G) R98.2
Schematic09/N68: CON7.3(G/M) CON7.6(GND) CON7.7(MS) R99.1
Schematic09/RAUXI: C41.2 CN1.3
Schematic09/RAUXIN: C41.1 U11.20(RAUXIN)
Schematic09/RHP: C36.1 U11.29(RHP)
Schematic09/RMICN: T2.\ U11.5(RMICN)
Schematic09/RMICP: C49.2 U11.4(RMICP)
Schematic09/RSPKOUT: CON6.1 U11.23(RSP_O)
Schematic09/SCL0: JP8.1 R66.2 R68.2
Schematic09/SDA0: JP7.1 R67.2 R70.2
Schematic09/VREF: C32.2 U11.27(VREF)
Schematic11/RX4: NU4.4(D3) R82.1 R85.2
Schematic11/RX5: NU2.4(D11/PWM1) R83.1 R86.2
Schematic11/RX7: NU3.6(ADC5) R81.1 R84.2
Schematic11/TX4: NU4.3(D2) R76.2 R79.2
Schematic11/TX5: NU2.5(D12/PWM2) R77.2 R80.2
Schematic11/TX7: NU3.5(ADC4) R75.2 R78.2
Schematic12/DM: CON9.A7(D-) CON9.B7(D-) R93.2
Schematic12/DP: CON9.A6(D+) CON9.B6(D+) R94.2
Schematic12/USB0_CC1: CON9.A5(CC1) Q6.3(D) Q8.3(DRAIN)
Schematic12/USB0_CC2: CON9.B5(CC2) Q7.3(D) Q9.3(DRAIN)
Schematic13/CAN0_H: CON15.1 R135.1 U15.7(CANH)
Schematic13/CAN0_L: CON15.2 R135.2 U15.6(CANL)
Schematic13/CAN0_RS: R140.1 U15.8(Rs)
Schematic13/CAN0_RXD: JP10.3 U15.4(R)
Schematic13/CAN0_TXD: JP11.3 U15.1(D)
Schematic13/EBI_DATA0: CON11.1 JP12.1
Schematic13/EBI_DATA3: CON11.4 JP10.1
Schematic13/EBI_DATA4: CON11.5 JP11.1
SP_VD33: CB31.1 CT26.1 R61.1 U11.26(VDDSPK)
USB0_DM: R93.1 U5.124(USB0_DM)
USB0_DP: R94.1 U5.125(USB0_DP)
USB0_ID: JP1.1 Q6.1(G) Q7.1(G) Q8.1(GATE) Q9.1(GATE) R91.1 R95.2 U5.1(USB0_ID)
USB0_REXT: R19.1 U5.127(USB0_REXT)
USB1_DM: R96.2 U5.119(USB1_DM)
USB1_DP: R97.2 U5.120(USB1_DP)
USB1_REXT: R20.1 U5.122(USB1_REXT)
VD12: CB11.1 CB12.1 CB13.1 CB14.1 CB15.1 CB16.1 CB17.1 CT14.1 CT15.1 CT16.1 CT17.1 L6.2 U5.10(VDD) U5.13(VDD) U5.43(VDD) U5.82(VDD) U5.94(VDD) U5.118(VDD) U5.123(USB0_VDD)
VD18: CB18.1 CB19.1 CT18.1 CT19.1 L7.2 U5.11(MVDD) U5.12(MVDD) U5.83(MVDD) U5.84(MVDD)
VD33: CB3.1 CB4.1 CB5.1 CB6.1 CB7.1 CB8.1 CB9.1 CT12.1 L4.2 L5.1 U5.9(VDDIO) U5.20(VDDIO) U5.60(VDDIO) U5.85(VDDIO) U5.102(VDDIO) U5.121(USB1_VDD33) U5.126(USB0_VDD33)
VD33_ADC: CB10.1 CT13.1 L5.2 NU2.8(VREF) U5.33(AVDDADC)
VD33_RTC: CB2.1 D3.2(1) D4.2(1) U5.39(VBAT33)
N16831709: LED1.1(ANODE) R5.1
N16831711: LED2.1(ANODE) R13.1
Schematic02/N16778107: LED1.2(CATHODE) U1.4(#Fault)
Schematic02/N16778127: R3.1 U1.7(Ilimit)
Schematic02/N16778208: R2.1 U1.5(#En) U1.6(Bat)
Schematic02/N16784849: D4.1(2) JP15.1
Schematic02/N16811538: C4.1 CT8.1 L2.2 R11.2 R101.1
Schematic02/N16811542: C2.1 R7.1 R8.2 U2.5(FB)
Schematic02/N16811544: C6.1 CT11.1 L3.2 R16.2 R102.1
Schematic02/N16811556: R15.2 U4.4(Vin)
Schematic02/N16811568: R10.2 U3.4(Vin)
Schematic02/N16811584: C5.1 R9.1 U3.1(EN)
Schematic02/N16811635: C2.2 CT5.1 L1.2 R7.2 R100.1
Schematic02/N16811664: C4.2 R11.1 R12.1 U3.5(FB)
Schematic02/N16811666: C7.1 R14.1 U4.1(EN)
Schematic02/N16811688: L3.1 U4.3(SW)
Schematic02/N16811702: L2.1 U3.3(SW)
Schematic02/N16811722: C6.2 R16.1 R17.1 U4.5(FB)
Schematic02/N16811955: R6.2 U2.4(Vin)
Schematic02/N16811975: L1.1 U2.3(SW)
Schematic02/N16811977: C3.1 R4.1 U2.1(EN)
Schematic05/N16777810: CON12.7 R33.2
Schematic05/N16803129: C13.1 Q1.BASE R34.1
Schematic05/N16807178: LED4.1 R29.1
Schematic05/N16809522: LED3.1 R28.1
Schematic05/N16830171: R22.2 SW1.3(B2)
Schematic05/N16830176: R23.2 SW1.4(B1)
Schematic05/N16837800: C12.2 L8.1 R31.2
Schematic05/N16846733: LED5.1 R30.1
Schematic06/N16765798: C18.2 U6.6(LDO_OUT)
Schematic06/N16805565: CON4.1(Shield) CON4.2(Shield) CON4.3(Shield) CON4.4(Shield) L9.2
Schematic06/N17128688: C15.1 U6.10(USB_LDO_OUT)
Schematic07/N16791552: R44.2 U7.3(/Rst)
Schematic08/N43037: C29.1 CB28.1 U10.2(CT)
Schematic08/N43057: C30.1 C31.1 CON5.13(Shield) CON5.14(Shield)
Schematic08/N43187: R59.2 U10.10(CT)
Schematic08/N43211: R60.2 U10.15(CT)
Schematic08/N43221: CON5.7(NC) CON5.8(NC) R57.2
Schematic08/N43237: CON5.4(NC) CON5.5(NC) R58.2
Schematic08/N44057: C28.1 CB27.1 U10.7(CT)
Schematic08/N44589: R45.2 U9.25(Iset)
Schematic08/N44889: CON5.9(LED-) R52.2
Schematic08/N45241: C30.2 R57.1 R58.1 R59.1 R60.1
Schematic08/N78875: CON5.12(LED+) R51.2
Schematic09/N16836167: C34.2 M1.N(2) R64.2
Schematic09/N16836169: C35.2 M1.P(1) R63.1
Schematic09/N16836231: R62.1 U11.32(MICBIAS)
Schematic10/N16777121: CON8.10(GND) CON8.11(GND) CON8.12(GND) CON8.13(GND) L16.1
Schematic10/N16777125: CON8.6(VSS) L13.2
Schematic10/N16777221: C44.1 CON8.5(CLK) R74.1
Schematic12/N16468590: CON10.4(GND) L15.2
Schematic12/N16468634: CON10.1(VBUS) CT28.2 F2.1
Schematic12/N16469044: CON10.2(D-) R96.1
Schematic12/N16469048: CON10.3(D+) R97.1
Schematic12/N16469082: C48.1 CON10.5(Shield) CON10.6(Shield)
Schematic12/N16571568: Q5.COLLECTOR R88.1 R90.2 U12.4(En)
Schematic12/N16571620: Q4.3(D) R87.2
Schematic12/N16571722: Q5.BASE R95.1
Schematic12/N16571856: Q4.1(G) R90.1
Schematic12/N16576405: CON9.1(Shield) CON9.2(Shield) CON9.3(Shield) CON9.4(Shield) L14.2
Schematic12/N16578005: Q9.2(SOURCE) R151.1
Schematic12/N16578138: Q8.2(SOURCE) R150.1
Schematic12/N16578544: Q6.2(S) R148.2
Schematic12/N16578548: Q7.2(S) R149.2

Not connected (* = marked no-connect by the designer): CON4 A2(TX1+)* A3(TX1-)* A8(SBU1) A10(RX2-)* A11(RX2+)* B2(TX2+)* B3(TX2-)* B8(SBU2)* B10(RX1-)* B11(RX1+)*; CON9 A2(TX1+)* A3(TX1-)* A8(SBU1) A10(RX2-)* A11(RX2+)* B2(TX2+)* B3(TX2-)* B8(SBU2)* B10(RX1-)* B11(RX1+)*; K1 1* 3; K2 1* 3; K3 1* 4*; NU1 1(NC)*; NU5 5(RESET)* 8(GPIO)*; RR1 7(R4)*; RR2 7(R4)*; U1 3(N.C.)*; U6 1(INT0/PB.14)* 2(I2C1_SCL/PA.11)* 3(I2C1_SDA/PA.10)* 13(MOSI0_0/PC.3)* 14(MISO0_0/PC.2)* 15(SPI0_CLK/PC.1)* 16(SPI0_CS0/PC.0)* 17(MOSI1_1/PC.13)* 18(MISO1_1/PC.12)* 19(MOSI1_0/PC.11)* 20(MISO1_0/PC.10)* 21(SPI1_CLK/PC.9)* 22(SPI1_CS0/PC.8)* 26(SPI2_CLK/PD.1)* 27(MISO2_0/PD.2)* 28(MOSI2_0/PD.3)*; U7 4(NC)* 5(NC)* 6(NC)* 11(NC)* 12(NC)* 13(NC)* 14(NC)*; U9 1(TxEr/FxSD)* 6(TxD3)* 7(TxD2)* 15(RxD3)* 16(RxD2)* 24(TestOn); U10 4(NC)* 5(NC)* 12(NC)* 13(NC)*; U11 6(RLIN/GPIO3)* 15(CSB/GPIO1)*; U12 5(\\~{O}C); U13 5(Vref)*; U14 5(Vref)*; U15 5(Vref)*; U16 5(Vref)*

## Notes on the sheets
sheet 2
- SCK2 ADC5
- VDD33
- SDA2 ADC7
- RESET
- VDD33
- AVDD33
- GND
- VIN5
- SCK PWM11
- GND
- DI PWM13 TX5
- GND
- DO PWM12 RX5
- VIN5
- SS PWM10
- PWM2
- PWM3
- TX5 PWM11
- ADC1 TX9
- ADC3 RX9
- RX5 PWM10
- SCL3 PWM2
- ADC2
- SDA3 PWM3
- ADC0
- RX4 PWM1
- ADC6 SDA1 TX7
- TX4 PWM0
- ADC4 SCL1 RX7
- TX1 PWM11
- RX1 PWM10
- DI0
- CLK0
- DO0
- SS0
sheet 3
- SD1/eMMC1
sheet 4
- Ethernet0_PE
sheet 6
- Speaker
- Microphone
- Earphone
- (EPAD = VSSA)
- 3
- MS
- 1
- 4
- 2
- 6
- 5
- CTIA
- L
- R
- GND
- MIC
- I2S
- CAN_3
- H
- CAN
- L
sheet 7
- QSPI0_Flash
sheet 8
- CAN_0
- H
- CAN
- L
- EBI_Connect
sheet 9
- PIN
- FUNCTION
- PIN
- FUNCTION
- PIN
- FUNCTION
- PIN
- FUNCTION
- PIN
- FUNCTION
- PIN
- FUNCTION
- PIN
- FUNCTION
- PA0
- I2C0_SDA
  CAN3_RXD
- PB0
- ADC_AIN[0]
- PC0
- EBI_DATA0
  CAN2_TXD
- PD2
- QSPI0_SS0
- PE0
- RMII0_RXERR
- PF0
- SD1_CMD
  eMMC1_CMD
- PG0
- CFG[0]
- I2C0_SCL
  CAN3_TXD
- SD1_CLK
  eMMC1_CLK
- PA1
- PB1
- ADC_AIN[1]
  UART9_TXD
- PC1
- EBI_DATA1
- PD3
- QSPI0_CLK
- PE1
- RMII0_CRSDV
- PF1
- PG1
- CFG[1]
- SD1_DATA0
  eMMC1_DATA0
- PA2
- I2S_LRCK
- PB2
- ADC_AIN[2]
- PC2
- EBI_DATA2
- PD4
- QSPI0_DO
- PE2
- RMII0_RXD1
- PF2
- PG3
- CFG[3]
- EBI_DATA3
  CAN0_RXD
- SD1_DATA1
  eMMC1_DATA1
- PA3
- I2S_BCLK
- PB3
- ADC_AIN[3]
  UART9_RXD
- PC3
- PD5
- QSPI0_DI
- PE3
- RMII0_RXD0
- PF3
- PG5
- CFG[5]
- EBI_DATA4
  CAN0_TXD
- SD1_DATA2
  eMMC1_DATA2
- UART5_RXD
- PA4
- I2S_DI
- I2C1_SCL
  ADC_AIN[4]
  UART7_RXD
- PC4
- PD6
- QSPI0_D2
- PE4
- RMII0_REFCLK
- PF4
- PG6
- PWM10
- PB4
- SD1_DATA3
  eMMC1_DATA3
- PA5
- I2S_DO
- PC5
- EBI_DATA5
- PD7
- QSPI0_D3
- PE5
- RMII0_TXEN
- PF5
- UART5_TXD
- PG7
- PWM11
- PA6
- I2S_MCLK
- I2C2_SCL
  ADC_AIN[5]
- PC6
- EBI_DATA6
- PD8
- SPI0_SS0
- PE6
- RMII0_TXD1
- PF6
- SD1_nCD
- PB5
- PG8
- CFG[8]
- PA7
- EBI_nWE
- I2C1_SDA
  ADC_AIN[6]
  UART7_TXD
- PC7
- EBI_DATA7
- PD9
- SPI0_CLK
- PE7
- RMII0_TXD0
- PF7
- PWM02
- PB6
- PG9
- CFG[9]
- PA8
- EBI_nRE
- PC8
- EBI_DATA8
- PD10
- SPI0_DO
  UART6_TXD
- PE8
- RMII0_MDIO
- PF8
- PWM03
- I2C2_SDA
  ADC_AIN[7]
- UART1_RXD
  PWM10
- PG11
- JTAG0_TDO
  SPI1_SS0
  PWM10
- PA9
- EBI_nCS0
- PB7
- PC9
- EBI_DATA9
- PE9
- RMII0_MDC
- PF9
- PD11
- SPI0_DI
  UART6_RXD
- EBI_ADDR10
  (LCD_RS)
- LED_Y
  CAN2_RXD
- UART1_TXD
  PWM11
- JTAG0_TCK
  SPI1_CLK
  PWM11
- PA10
- PB8
- PC10
- EBI_DATA10
- PE10
- Key1
- PF10
- PG12
- PA11
- EBI_ADDR9
  (LCD_RESET)
- PB13
- LED_R
- PC11
- EBI_DATA11
- PD12
- UART4_TXD
  PWM00
- PE11
- USB0_VBUSVLD
- PF11
- UART0_RXD
- JTAG0_TMS
  SPI1_DO
  PWM12
  UART5_RXD
  CAN1_RXD
- PG13
- EBI_ADDR8
  (LCD_BL)
- PA12
- PC12
- EBI_DATA12
- PD13
- UART4_RXD
  PWM01
- PE12
- Key2
- PF12
- UART0_TXD
- PC13
- EBI_DATA13
- PD14
- I2C3_SCL
  PWM02
- PG14
- JTAG0_TDI
  SPI1_DI
  PWM13
  UART5_TXD
  CAN1_TXD
- PC14
- EBI_DATA14
- PD15
- I2C3_SDA
  PWM03
- PC15
- EBI_DATA15
- JTAG0_NTRST
  LED_G
- PG15
sheet 10
- 5V IN
- VDD33
- P_Fault
- VDD18
- RTC Battery 3.3V
- +
- -
- VDD12
sheet 11
- PG1
- PG0
- Booting from
- Power On Setting
- ON(0)
- ON(0)
- USB
- ON(0)
- OFF(1)
- SD/eMMC
- K1
- OFF(1)
- OFF(1)
- OFF(1)
- ON(0)
- NAND Flash
- QSPI Flash_0
- PG3
- Watch Dog
- K2
- ON(0)
- OFF
- OFF(1)
- ON
- CAN_2
- ON(0)
- PG5
- ON
- UART0 Message
- OFF(1)
- OFF
- H
- PG9
- PG8
- QSPI Source if PG[1:0]=11
- ON(0)
- ON(0)
- SPI-NAND, 1-bit
- OFF(1)
- ON(0)
- OFF(1)
- OFF(1)
- ON(0)
- SPI-NAND, 4-bit
- SPI-NOR, 4-bit
- CAN
- OFF(1)
- OFF(1)
- SPI-NOR, 1-bit
- L
- LED3
- LED4
- LED5
- VDD33
- TRST
- TDI
- TMS
- TCK
- RES
- TDO
- TX0
- RX0
- VSS
- RESET
- CAN_1
- H
- CAN
- L
sheet 12
- USB0 Device/HOST
- USB0 HOST
- USB 2.0 HIGH SPEED DEVICES
- Type C Connector
- USB1 HOST
sheet 14
- 1
- VCOM
